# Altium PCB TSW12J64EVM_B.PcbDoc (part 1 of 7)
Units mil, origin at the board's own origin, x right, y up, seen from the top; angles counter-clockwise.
Board outline 8833 x 2680 mil, 10 copper layers (Top Layer L1, Gnd-Plane - L2, Signals - L3, Gnd-Plane - L4, Pwr Plane - L5, Signals - L6, Gnd-Plane - L7, Signals - L8, Gnd-Plane - L9, Bottom Layer - L10), stack 57.8 mil thick; 950 components, 533 nets, 2888 pads, 1732 vias.
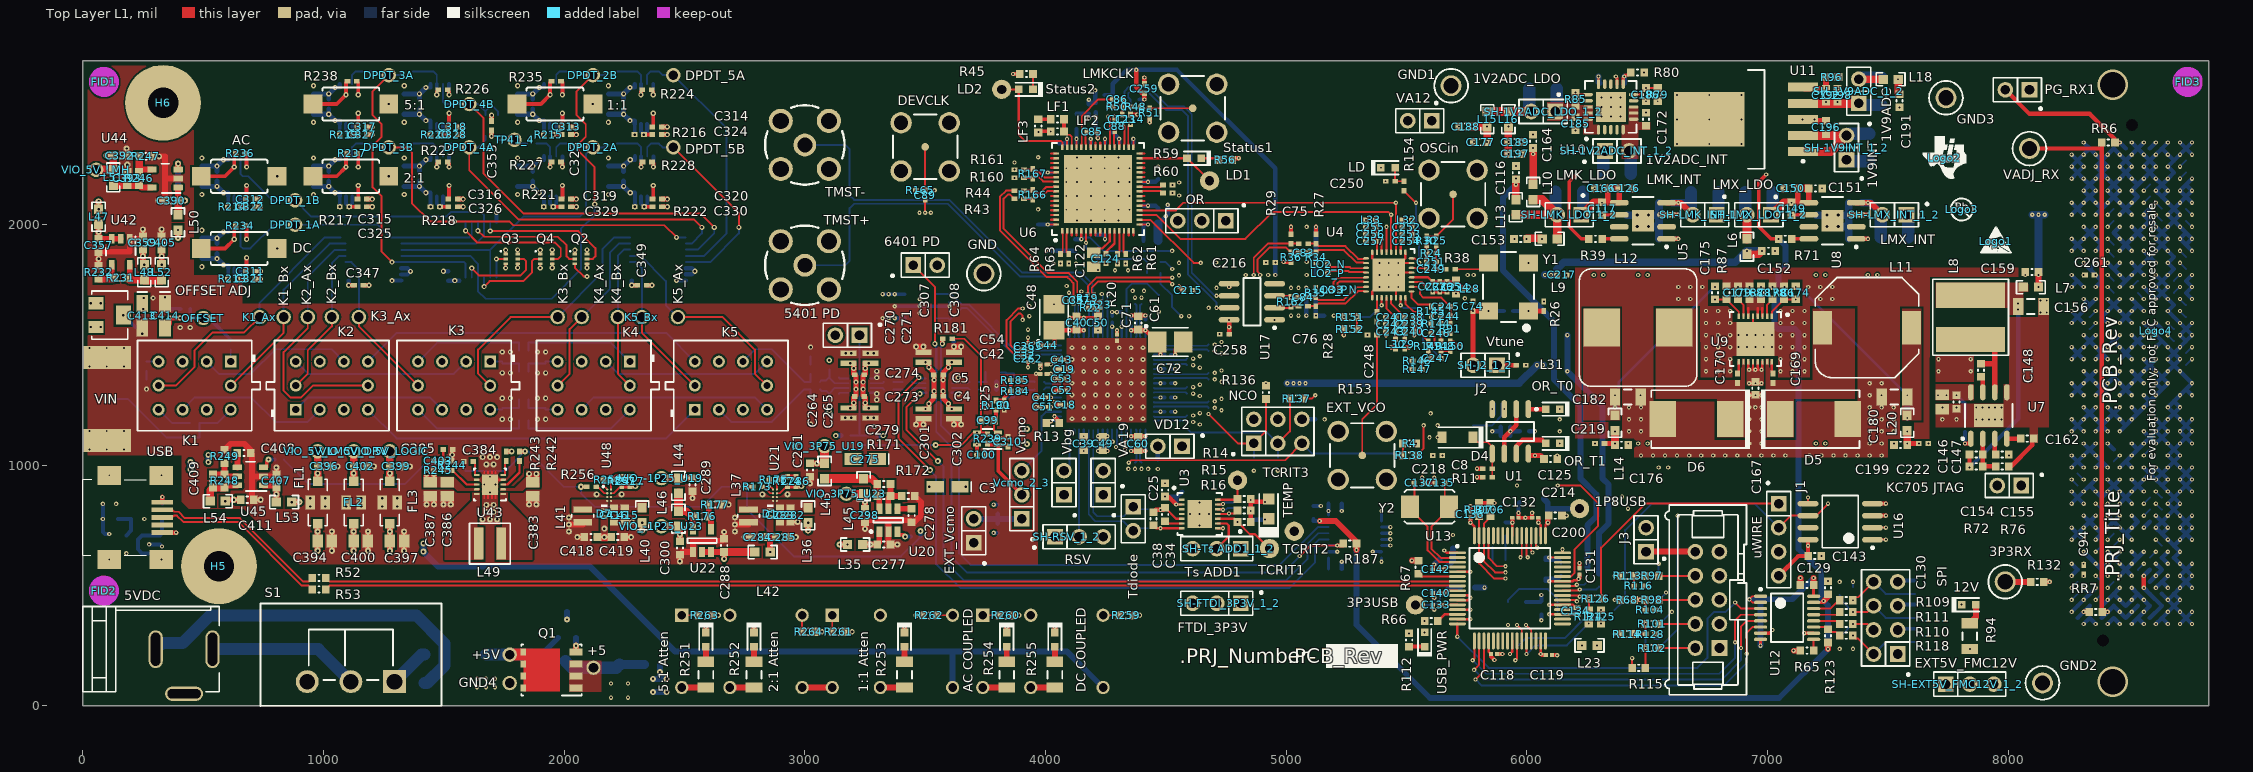
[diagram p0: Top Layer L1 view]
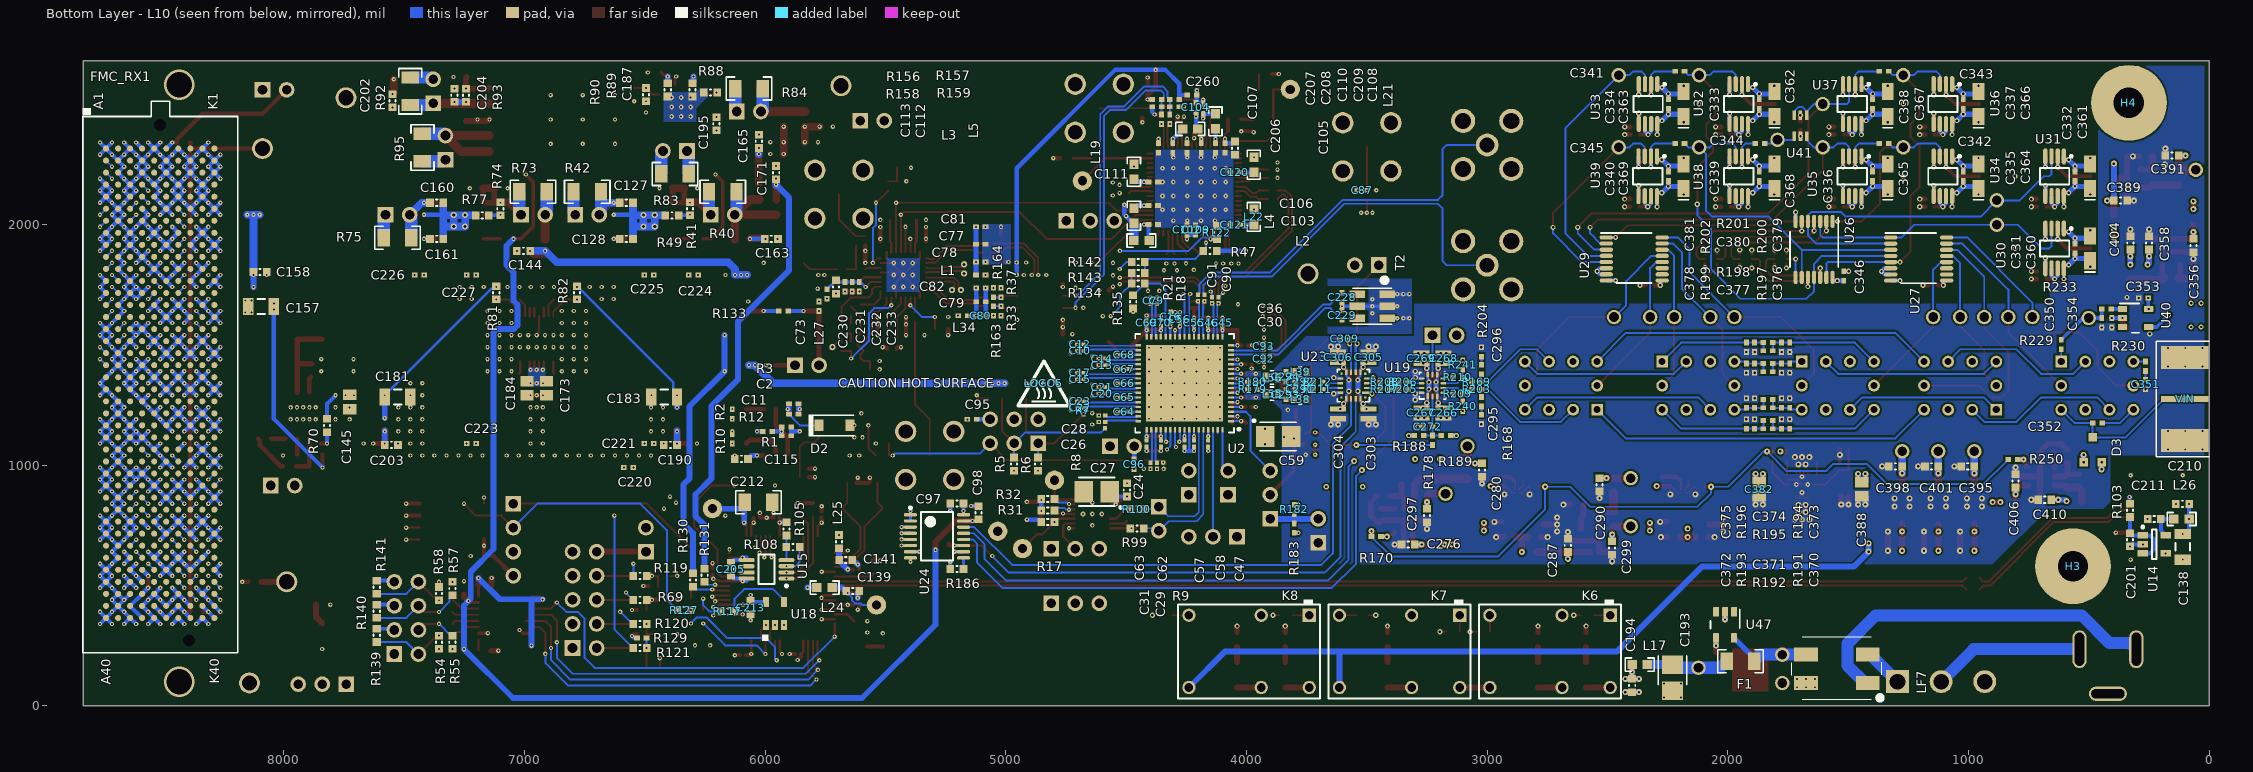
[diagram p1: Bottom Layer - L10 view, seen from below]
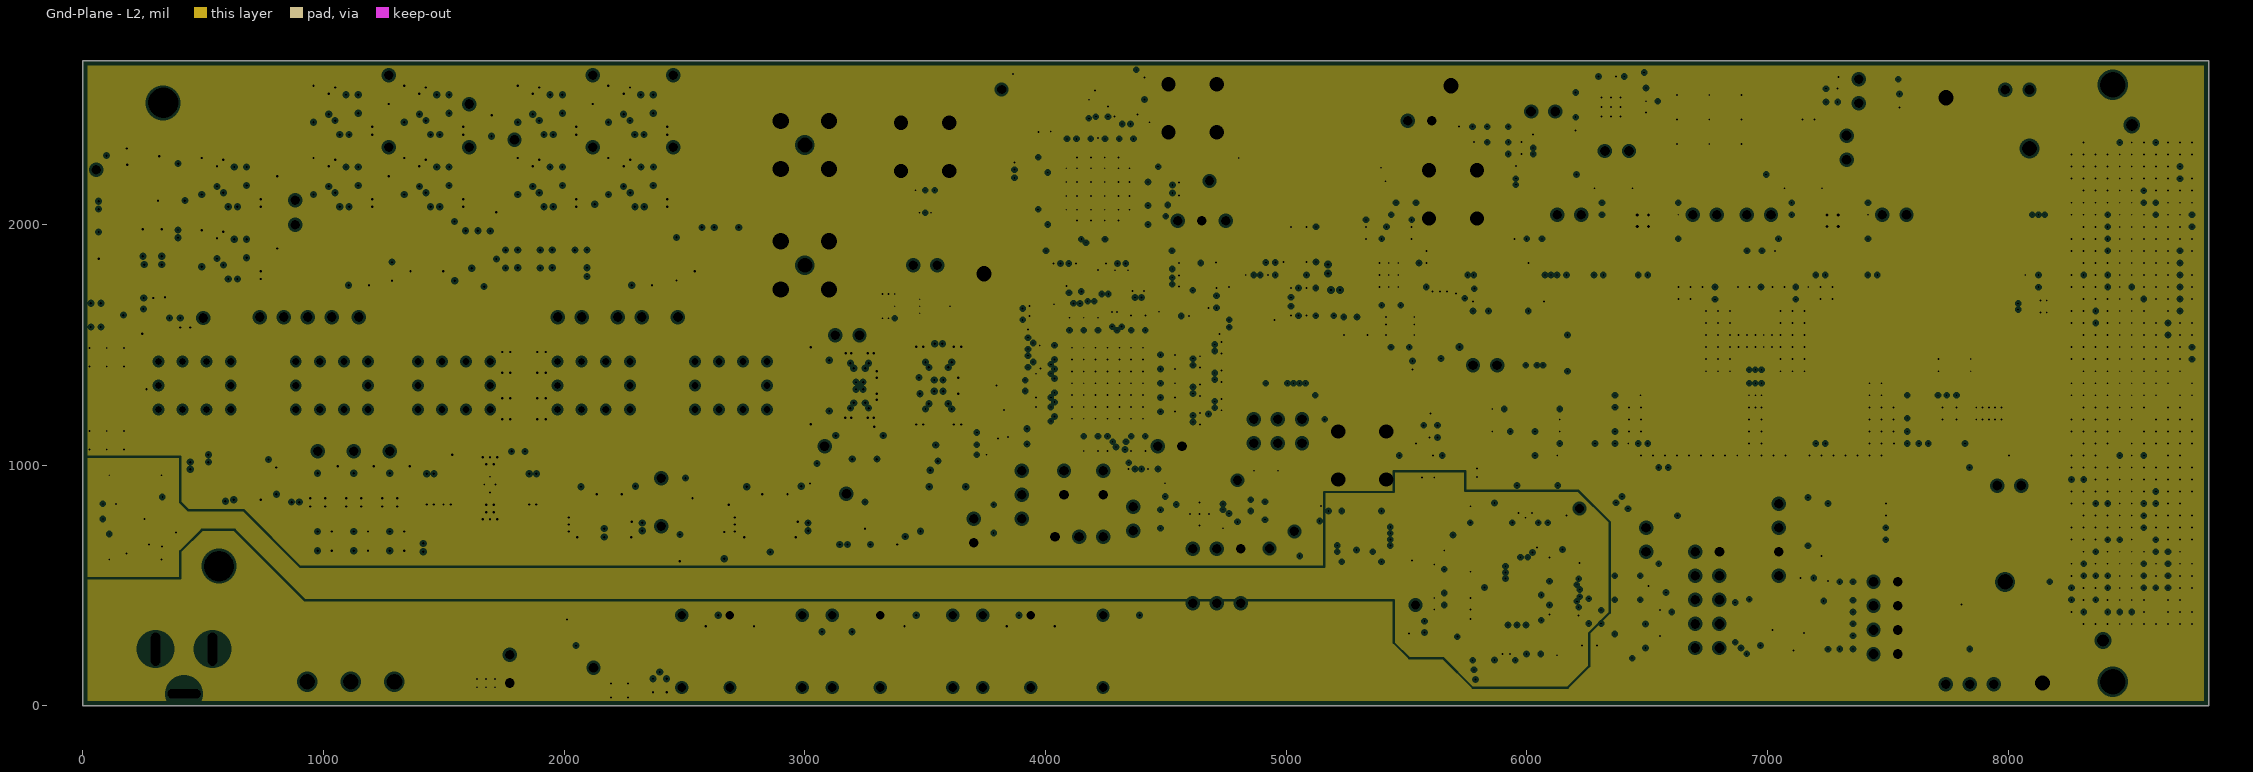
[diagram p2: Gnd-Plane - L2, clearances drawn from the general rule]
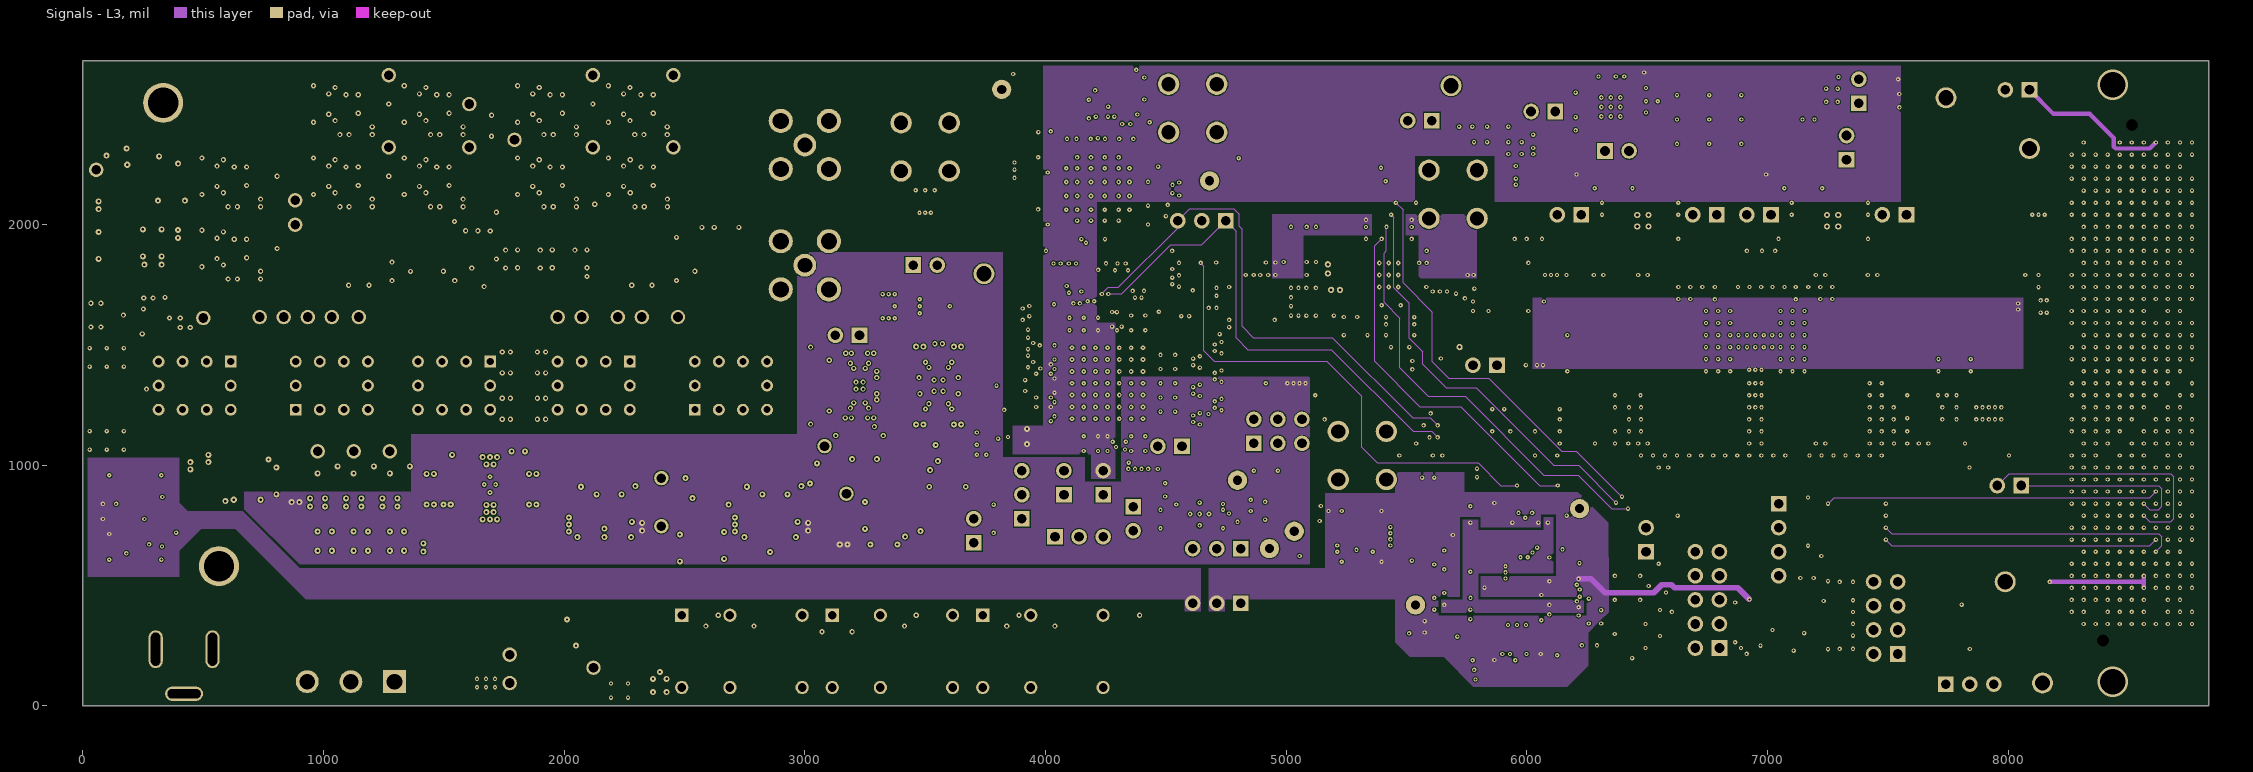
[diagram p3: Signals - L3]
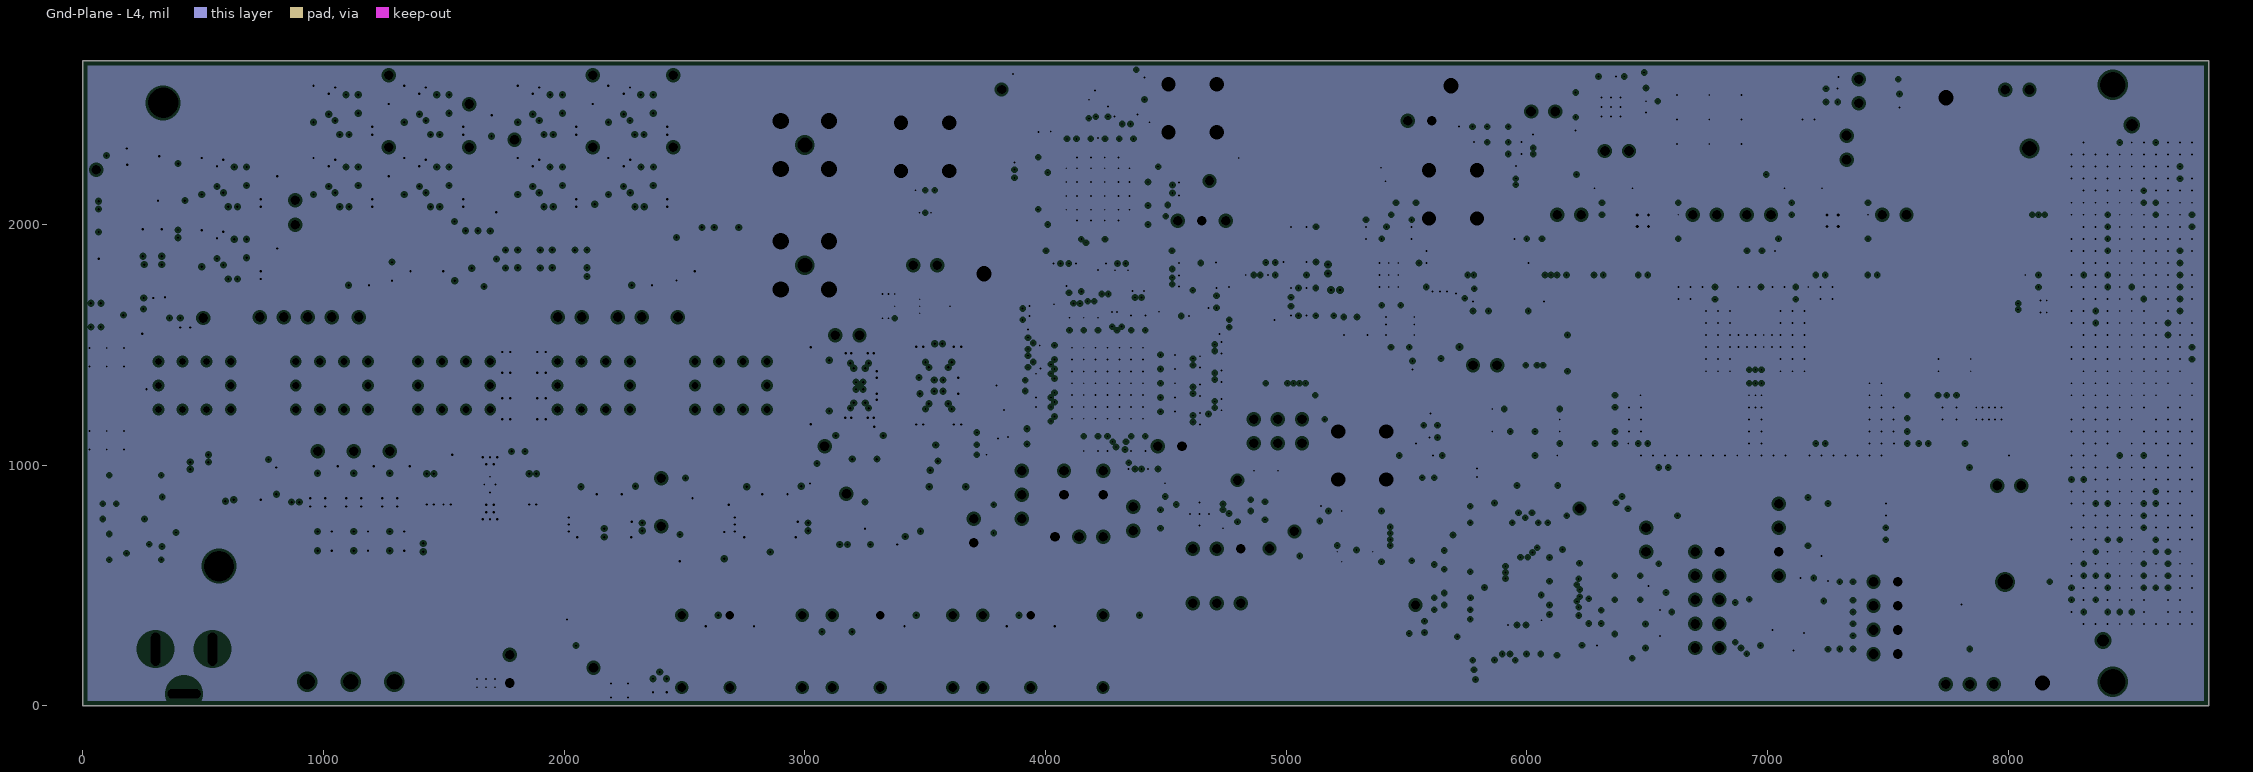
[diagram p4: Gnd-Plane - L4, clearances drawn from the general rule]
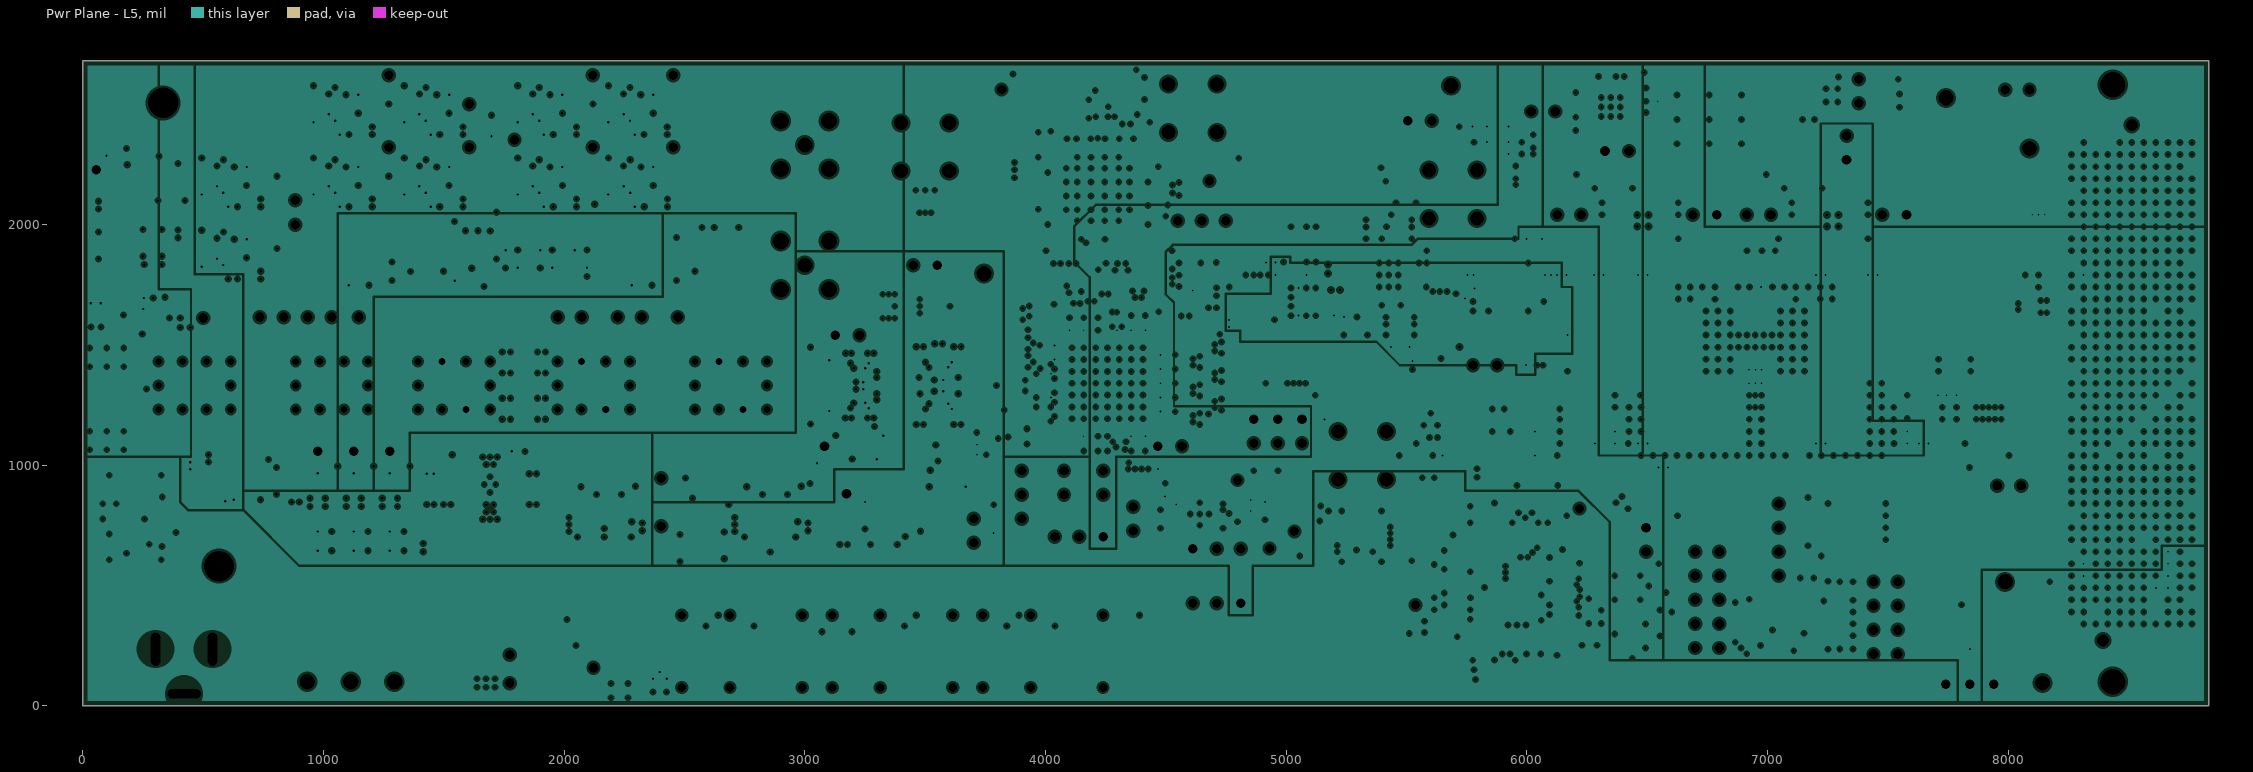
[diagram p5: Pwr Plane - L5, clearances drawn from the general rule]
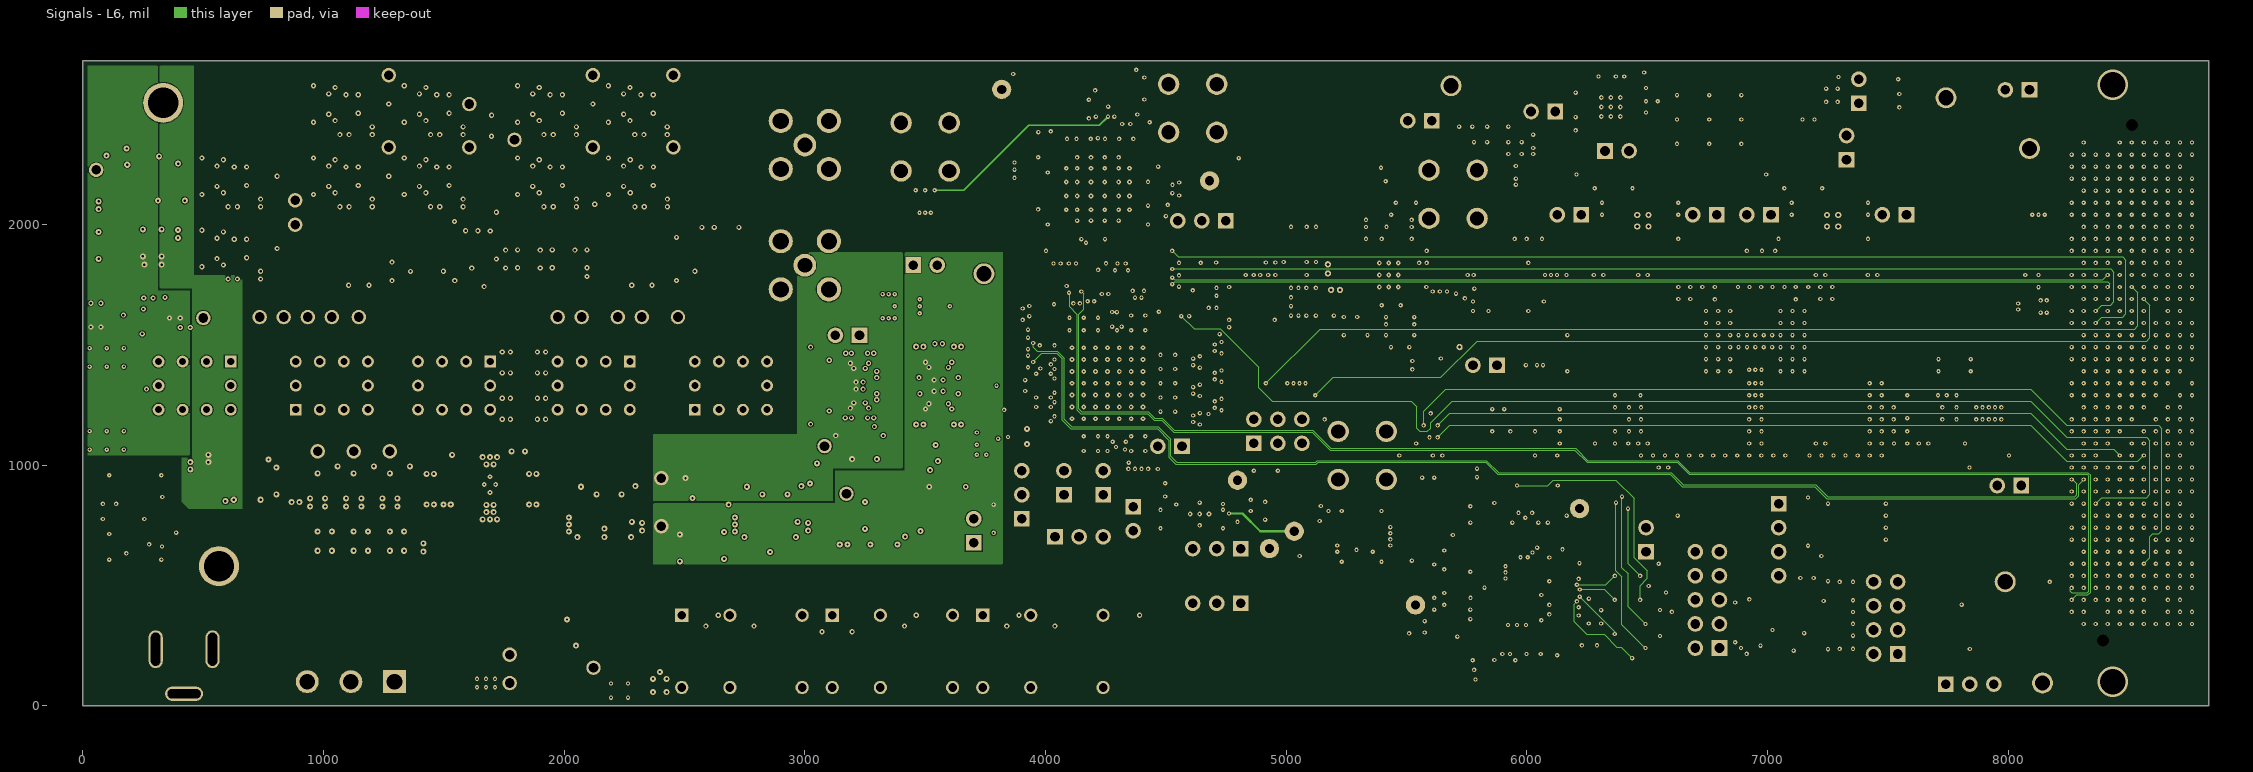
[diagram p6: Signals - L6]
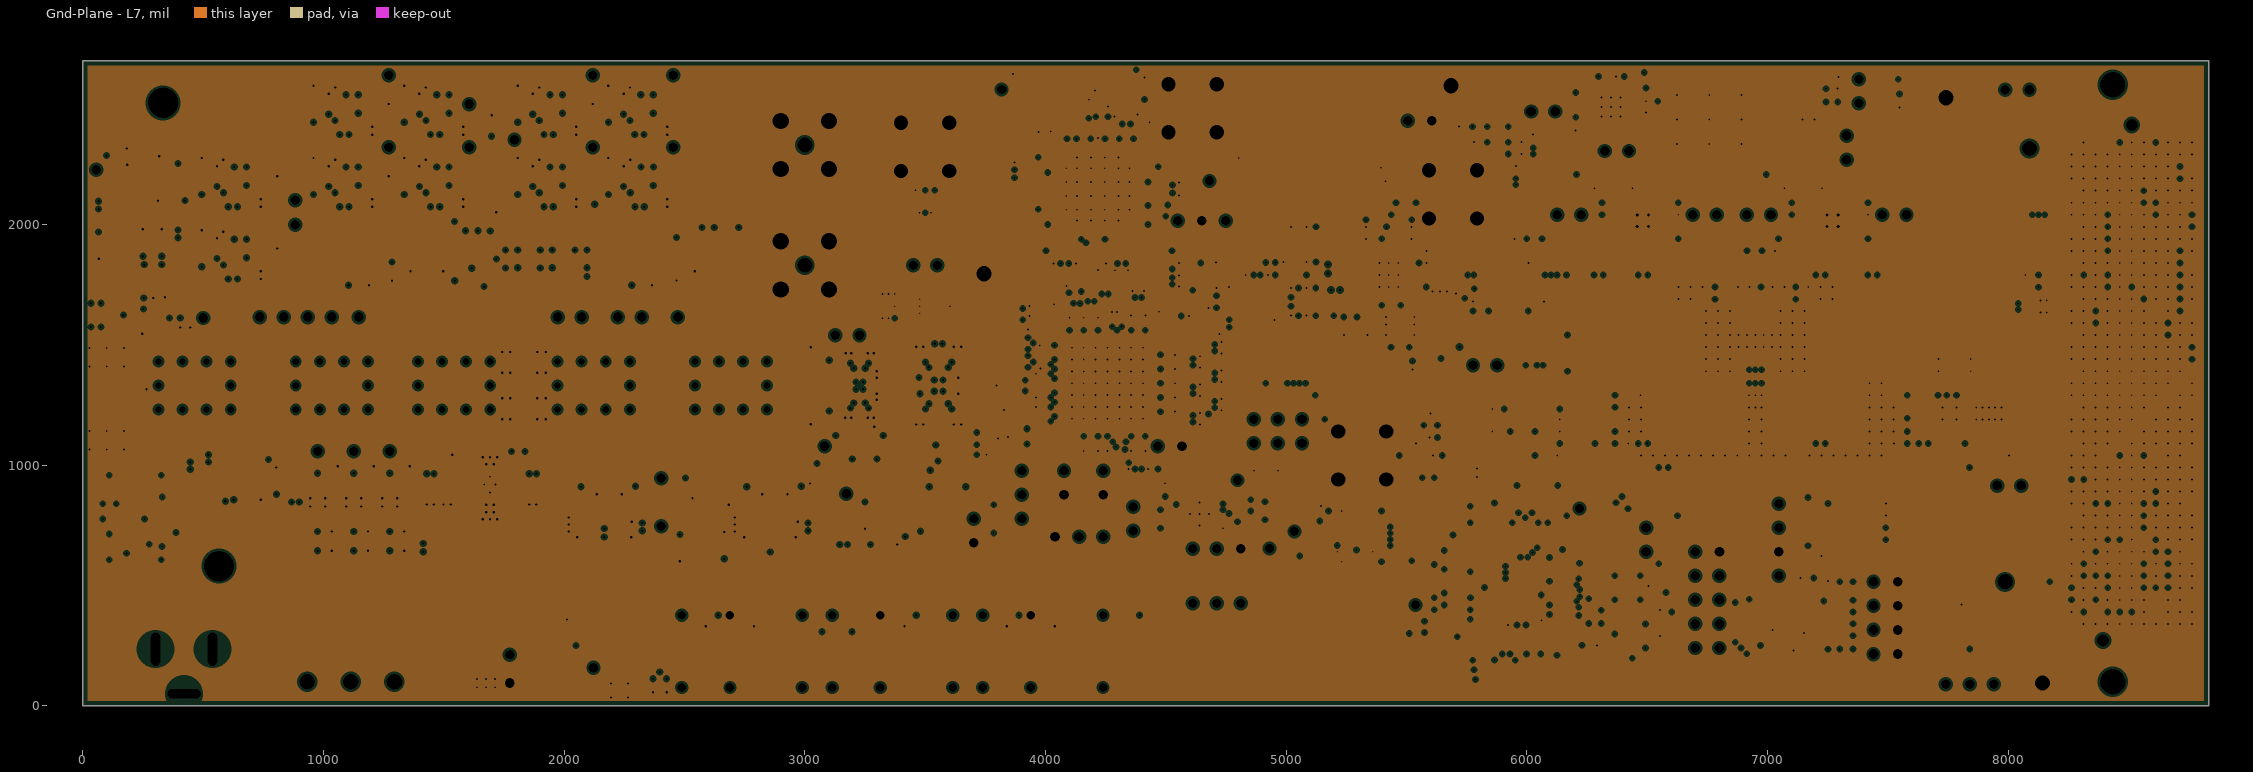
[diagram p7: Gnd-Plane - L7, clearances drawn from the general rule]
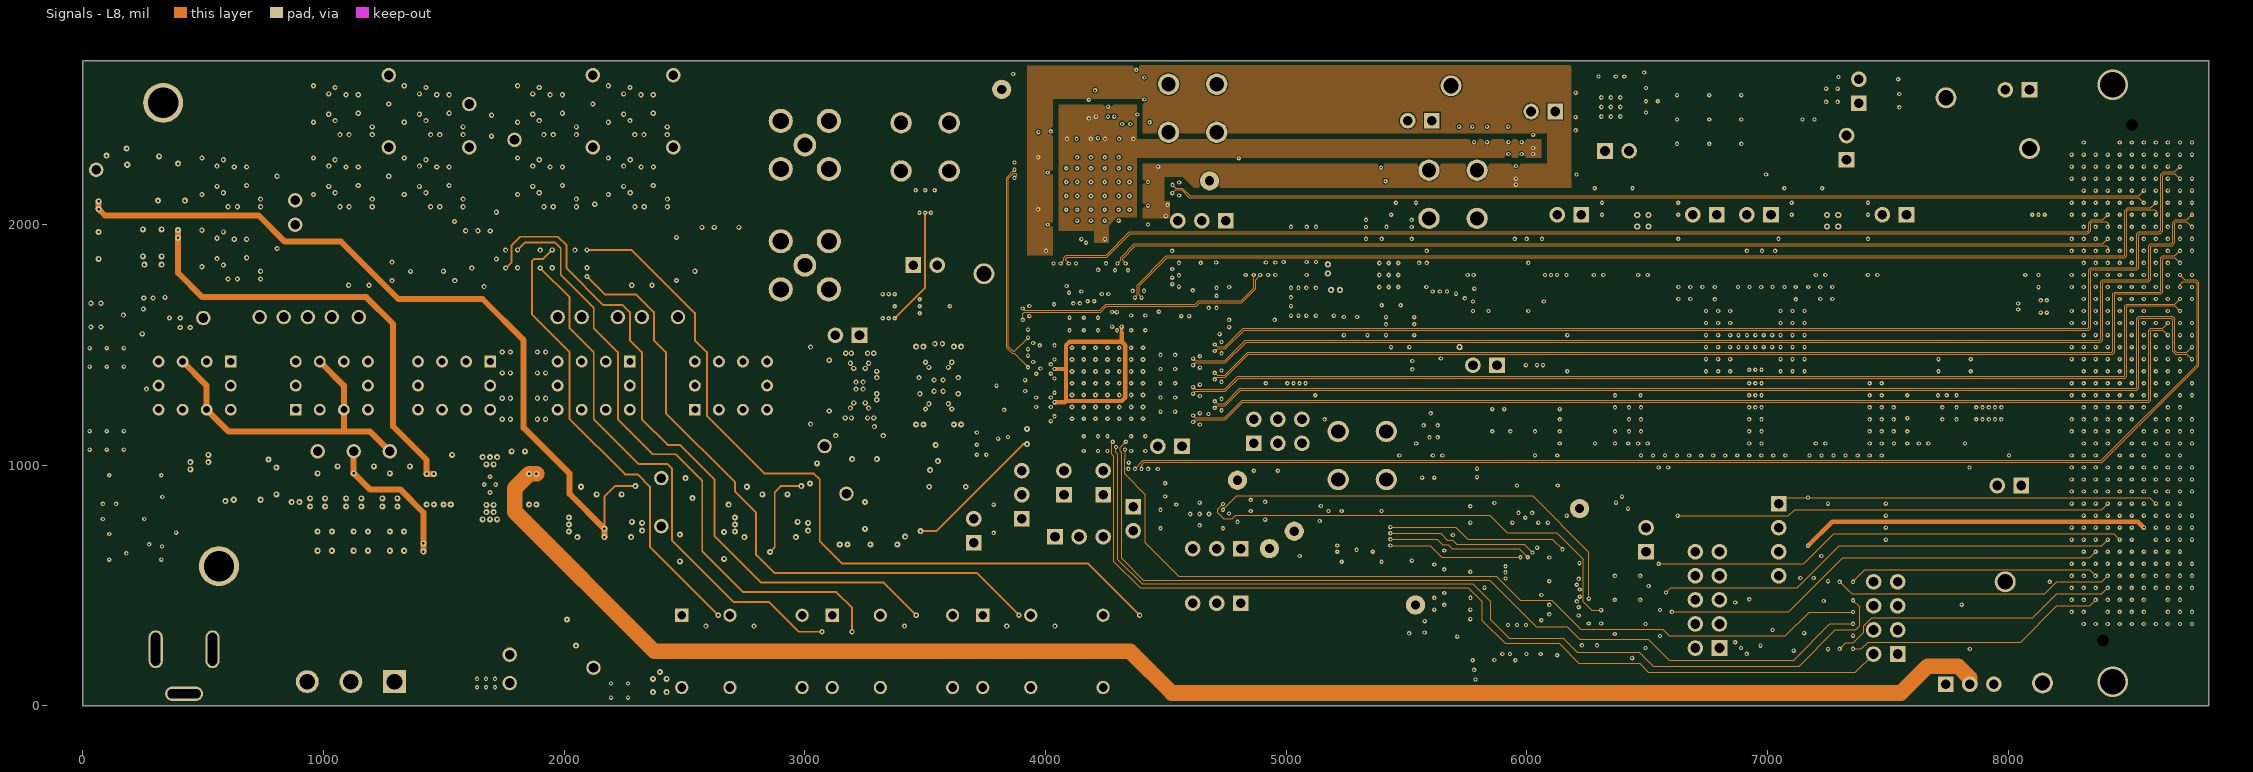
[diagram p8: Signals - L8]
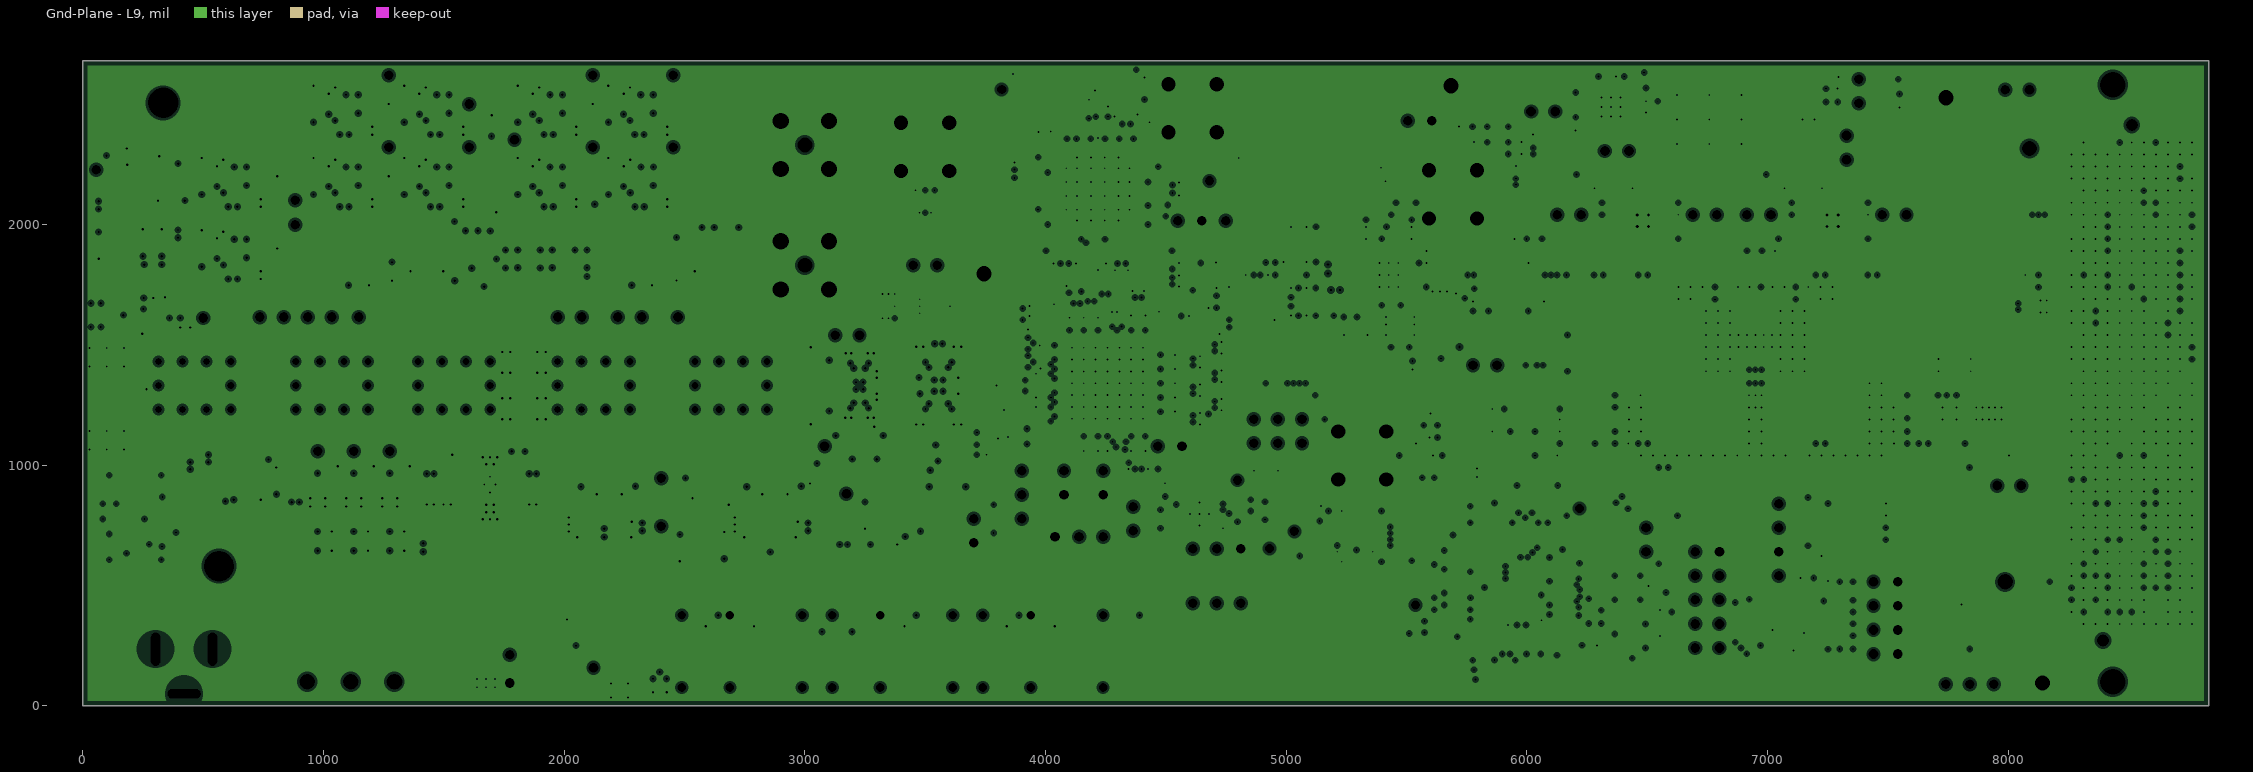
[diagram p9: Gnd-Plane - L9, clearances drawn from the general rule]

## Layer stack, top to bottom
Top Solder: solder mask 0.4, Solder Resist, Dk 3.5
Top Layer L1: signal copper 0.6
Dielectric1: core 4, Rogers RO4350, Dk 3.66
Gnd-Plane - L2: plane copper 1.2, net (Multiple Nets)
Dielectric8: prepreg 6.7, NP 4000-6, Dk 4.11
Signals - L3: signal copper 0.6
Dielectric2: core 6, NP 4000-6, Dk 4.11
Gnd-Plane - L4: plane copper 1.2, net GND
Dielectric7: prepreg 4.1, NP 4000-6, Dk 4.11
Pwr Plane - L5: plane copper 1.2, net (Multiple Nets)
Dielectric9: core 6, NP 4000-6, Dk 4.11
Signals - L6: signal copper 0.6
Dielectric3: prepreg 6.7, NP 4000-6, Dk 4.11
Gnd-Plane - L7: plane copper 1.2, net GND
Dielectric6: core 4, Rogers RO4350, Dk 3.66
Signals - L8: signal copper 0.6
Dielectric4: prepreg 7.3, Rogers RO4350, Dk 3.66
Gnd-Plane - L9: plane copper 1.2, net GND
Dielectric5: core 4, Rogers RO4350, Dk 3.66
Bottom Layer - L10: signal copper 0.6
Bottom Solder: solder mask 0.4, Solder Resist, Dk 3.5

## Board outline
0,0 8833,0 8833,2680 0,2680

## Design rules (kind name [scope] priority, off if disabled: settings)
AcuteAngle [All] p1: minimum=4.50000000000000E+0001 checktracksonly=FALSE
AssemblyTestPointUsage [All] p1: valid=2
Clearance Clearance_3 [InNamedPolygon('Top Layer L1-VIO_1P9V')] p1: gap=10
Clearance Clearance_2 [InNamedPolygon('Top Layer - L1 - Anolog In GND')] p2: gap=8
Clearance Clearance_1 [InNamedPolygon('Bottom Layer - L10 - Anolog In GND')] p3: gap=8
Clearance "0201 PADS" [HasFootprint('0201') vs HasFootprint('0201')] p4: gap=7.87
Clearance Clearance_BoardEdge_MountingHoles [OnCopper and InComponentClass('Mounting Holes') vs IsKeepOut] p5: gap=40
Clearance Clearance_BoardEdge_Poly [OnCopper and InPoly vs IsKeepOut] p6: gap=25
Clearance Clearance_BoardEdge [OnCopper and Not InComponentClass('Logo') and not InComponentClass('FiducialMark') and not InRegion(1000,500,4000,800) and Not IsKeepout vs IsKeepOut] p7: gap=25
Clearance [All] p8: gap=4
ComponentClearance ComponentClearance_R239_U25 [InComponent('R239') or InComponent('U25') vs InComponent('R239') or InComponent('U25')] p1: gap=0 collisioncheckmode=3 verticalgap=0 showdistances=FALSE
ComponentClearance ComponentClearance_FID2_5VDC [(InComponent('FID2') OR InComponent('5VDC'))] p2: gap=3.28 collisioncheckmode=3 verticalgap=3.28 showdistances=FALSE
ComponentClearance ComponentClearance_4-40_Screw [(HasFootprint('NY PMS 440 0025 PH'))] p3: gap=5 collisioncheckmode=3 verticalgap=10 showdistances=FALSE
ComponentClearance ComponentClearance_TestPoint [HasFootprint('TESTPOINT')] p4: gap=3.5 collisioncheckmode=3 verticalgap=10 showdistances=FALSE
ComponentClearance ComponentClearance_Shared_Pad [(InComponent('R7') OR InComponent('R8') OR InComponent('R9') OR InComponent('C22') OR InComponent('C26') OR InComponent('C29') OR InComponent('SH-*') OR InComponent('RSV*') OR InComponent('Ts ADD1*') OR InComponent('LMX_INT*') OR InComponent('LMX_LDO*') OR InComponent('LMK_INT*') OR InComponent('LMK_LDO*') OR InComponent('1V2ADC_INT*') OR InComponent('1V2ADC_LDO*') OR InComponent('1V9INT*') OR InComponent('1V9ADC*') OR InComponent('+12V*') OR InComponent('C32*') OR InComponent('C262*')OR InComponent('C33*') OR InComponent('C263*') OR InComponent('C92*') OR InComponent('C93*') OR InComponent('C89*') OR InComponent('R165*') OR InComponent('Vcmo_2_3*') OR InComponent('Vcmo*'))] p5: gap=0 collisioncheckmode=3 verticalgap=0 showdistances=FALSE
ComponentClearance ComponentClearance_0201 [HasFootprint('0201*') or HasFootprint('LQA68A') vs HasFootprint('0201*') or HasFootprint('LQA68A')] p6: gap=10 collisioncheckmode=3 verticalgap=10 showdistances=FALSE
ComponentClearance ComponentClearance_ScrewToNut [(HasFootprint('NY PMS 440 0025 PH')) vs (HasFootprint('Keystone_1902C'))] p7: gap=5 collisioncheckmode=3 verticalgap=10 showdistances=FALSE
ComponentClearance ComponentClearance_MountingHoles [InComponentClass('Mounting Holes')] p8: gap=250 collisioncheckmode=3 verticalgap=100000 showdistances=FALSE
ComponentClearance ComponentClearance_SmallPassives [HasFootprint('0201*') or HasFootprint('0402*') or HasFootprint('0508') or HasFootprint('0603*') or HasFootprint('0612') or HasFootprint('0805*') or HasFootprint('0815*') or HasFootprint('0830*') or HasFootprint('1206*') or HasFootprint('1210*') or HasFootprint('1808*') or HasFootprint('1812*') or HasFootprint('1825*') or HasFootprint('2010*') or HasFootprint('2220*') or HasFootprint('2225*') or HasFootprint('2512*') or HasFootprint('2728*') or HasFootprint('3518*') or HasFootprint('LQA68A*')  or HasFootprint('RTV0032A*') or HasFootprint('DBV0005A*') or HasFootprint('XTAL_ABM3*') or HasFootprint('RGW0020A*') or HasFootprint('M08A*') or HasFootprint('LED_LTST-C190*') or HasFootprint('DDA0008B*') or HasFootprint('SOIJ-SM8*') or HasFootprint('MSOP-MS8*') or HasFootprint('SDA16A*') or HasFootprint('OSC_CWX*') or HasFootprint('3528-21*') or HasFootprint('PW0016A*') or HasFootprint('MRA08A*') or HasFootprint('TJ5A*') or HasFootprint('SOD-123*') or HasFootprint('RLY0068A*') or HasFootprint('SOP-5_.95MM_(DBV)*') or HasFootprint('IND_2.0X2.0MM_A*') or HasFootprint('SOD-882*') or HasFootprint('YFX0008ADAC*') vs HasFootprint('0201*') or HasFootprint('0402*') or HasFootprint('0508') or HasFootprint('0603*') or HasFootprint('0612') or HasFootprint('0805*') or HasFootprint('0815*') or HasFootprint('0830*') or HasFootprint('1206*') or HasFootprint('1210*') or HasFootprint('1808*') or HasFootprint('1812*') or HasFootprint('1825*') or HasFootprint('2010*') or HasFootprint('2220*') or HasFootprint('2225*') or HasFootprint('2512*') or HasFootprint('2728*') or HasFootprint('3518*') or HasFootprint('LQA68A*')  or HasFootprint('RTV0032A*') or HasFootprint('DBV0005A*') or HasFootprint('XTAL_ABM3*') or HasFootprint('RGW0020A*') or HasFootprint('M08A*') or HasFootprint('LED_LTST-C190*') or HasFootprint('DDA0008B*') or HasFootprint('SOIJ-SM8*') or HasFootprint('MSOP-MS8*') or HasFootprint('SDA16A*') or HasFootprint('OSC_CWX*') or HasFootprint('3528-21*') or HasFootprint('PW0016A*') or HasFootprint('MRA08A*') or HasFootprint('TJ5A*') or HasFootprint('SOD-123*') or HasFootprint('RLY0068A*') or HasFootprint('SOP-5_.95MM_(DBV)*') or HasFootprint('IND_2.0X2.0MM_A*') or HasFootprint('SOD-882*') or HasFootprint('YFX0008ADAC*')] p9: gap=5 collisioncheckmode=3 verticalgap=5 showdistances=FALSE
ComponentClearance ComponentClearance_THtoSMT [IsThruComponent vs IsSMTComponent] p10: gap=10 collisioncheckmode=3 verticalgap=0 showdistances=FALSE
ComponentClearance ComponentClearance_THtoTH [IsThruComponent vs IsThruComponent] p11: gap=10 collisioncheckmode=3 verticalgap=100000 showdistances=FALSE
ComponentClearance [All] p12: gap=10 collisioncheckmode=3 verticalgap=10 showdistances=FALSE
DiffPairsRouting [All] p1: maxlimit=100 minlimit=4 mostfreqgap=4 toplayer_mingap=8 toplayer_prefgap=8 toplayer_minwidth=15 toplayer_maxwidth=15 toplayer_prefwidth=15 midlayer1_minwidth=15 midlayer1_maxwidth=15 midlayer1_prefwidth=15 midlayer2_minwidth=15 midlayer2_maxwidth=15 midlayer2_prefwidth=15 midlayer3_minwidth=15 midlayer3_maxwidth=15 midlayer3_prefwidth=15 bottomlayer_mingap=8 bottomlayer_prefgap=8 bottomlayer_minwidth=15 bottomlayer_maxwidth=15 bottomlayer_prefwidth=15 maxuncoupledlength=1000
FabricationTestPointUsage TestPointUsage [All] p1: valid=2 allowmultiple=FALSE
FabricationTestpoint Testpoint [All] p1: side=3 testpointundercomponent=TRUE minsize=40 maxsize=100 preferedsize=60 minholesize=0 maxholesize=40 preferedholesize=32 testpointgrid=1 allowsidetop=TRUE allowsidebottom=TRUE usegrid=TRUE gridtolerance=0.01
FanoutControl Fanout_LCC [IsLCC] p1: bgadir=Out bgaviamode=Centered fanoutstyle=Auto fanoutdirection=Alternating viagrid=1 // Fanout_LCC (Default Rule)
FanoutControl Fanout_BGA [IsBGA] p2: bgadir=Out bgaviamode=Centered fanoutstyle=Auto fanoutdirection=Alternating viagrid=1 // Fanout_BGA (Default Rule)
FanoutControl Fanout_Default [All] p4: bgadir=Out bgaviamode=Centered fanoutstyle=Auto fanoutdirection=Alternating viagrid=1 // Fanout_Default (Default Rule)
FanoutControl Fanout_Small [(CompPinCount < 5)] p5: bgadir=Out bgaviamode=Centered fanoutstyle=Auto fanoutdirection=OutThenIn viagrid=1 // Fanout_Small (Default Rule)
HoleSize [All] p1: absolutevalues=TRUE maxlimit=251 minlimit=7.87 maxpercent=80.000 minpercent=20.000
MinimumAnnularRing [All] p1: minimumring=5
MinimumSolderMaskSliver MinimumSolderMaskSliver_U21_U48 [All vs (InComponent('U21') OR InComponent('U48'))] p1: minsoldermaskwidth=3.74
MinimumSolderMaskSliver MinimumSolderMaskSliver_U19 [InComponent('U19')] p2: minsoldermaskwidth=3.5
MinimumSolderMaskSliver MinimumSolderMaskSliver_Logo [InComponentClass('Logo') vs InComponentClass('Logo')] p3: minsoldermaskwidth=0.7
MinimumSolderMaskSliver [All] p4: minsoldermaskwidth=4
NetAntennae "NetAntennae U2 or U6" [(InNet('U2-*') OR InNet('U6-*'))] p1: netantennaetolerance=50
NetAntennae [All] p2: netantennaetolerance=0
PlaneClearance [All] p1: clearance=10
PlaneConnect [All] p1: planeconnectstyle=Direct reliefexpansion=10 reliefentries=4 reliefconductorwidth=10 reliefairgap=10
PolygonConnect [All] p1: connectstyle=Direct reliefconductorwidth=10 reliefentries=4 polygonreliefangle="90 Angle" airgapwidth=10
RoutingVias [All] p1: holewidth=16 width=34 viastyle="Through Hole" minholewidth=7.87 minwidth=18 maxholewidth=106 maxwidth=126
SMDToCorner [All] p1: distance=30000
SilkToSilkClearance SilkToSilkClearance_Pb-FreeLogo [(HasFootprint('Pb-Free_Overlay_Medium') OR HasFootprint('Pb-Free_Overlay_Small')) vs (HasFootprint('Pb-Free_Overlay_Medium') OR HasFootprint('Pb-Free_Overlay_Small'))] p1: silktosilkclearance=0
SilkToSilkClearance [All] p2: silktosilkclearance=5
SilkToSolderMaskClearance SilkscreenOverComponentPads [IsPad] p1: minsilkscreentomaskgap=5 clearancetoexposedcopper=TRUE
SolderMaskExpansion [All] p1: expansion=3
UnpouredPolygon [All] p1: allowunpoured=FALSE
Width [All] p1: maxlimit=100 minlimit=4 preferedwidth=10 checkconnectedcopper=TRUE
13 further rules are at their usual default settings.

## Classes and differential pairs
component class AssemblyNote: !PCB H9 H10 H11 H12 ZZ2 ZZ3 ZZ4
component class Header: 1V2ADC_INT 1V2ADC_LDO 1V9ADC 1V9INT "5401 PD" "6401 PD" EXT5V_FMC12V EXT_Vcmo FTDI_3P3V J1 J2 J3 "KC705 JTAG" LMK_INT LMK_LDO LMX_INT LMX_LDO NCO OR PG_RX1 RSV SPI Tdiode "Ts ADD1" VA12 VA19 Vbg Vcmo VD12
component class Shunt: SH-1V2ADC_INT_1_2 SH-1V2ADC_LDO_1_2 SH-1V9ADC_1_2 SH-1V9INT_1_2 SH-EXT5V_FMC12V_1_2 SH-FTDI_3P3V_1_2 SH-J2_1_2 SH-LMK_INT_1_2 SH-LMK_LDO_1_2 SH-LMX_INT_1_2 SH-LMX_LDO_1_2 SH-RSV_1_2 "SH-Ts ADD1_1_2" Vcmo_2_3
component class 0402L: C1 C272 C309
component class FiducialMark: FID1 FID2 FID3
component class Logo: Logo2
component class "Mounting Holes": H5 H6
differential pair IN: +IN_P -IN_N
differential pair DEV_CLK: +DEV_CLK_P -DEV_CLK_N
differential pair CLK10: +CLK10_P -CLK10_N
differential pair TMST: +TMST_P -TMST_N
differential pair CLK3: +CLK3_P -CLK3_N
differential pair CLK11: +CLK11_P -CLK11_N
differential pair CLK0: +CLK0_P -CLK0_N
differential pair CLK4: +CLK4_P -CLK4_N
differential pair CLKIN1: +CLKIN1_P -CLKIN1_N
differential pair D0: +D0_P -D0_N
differential pair D1: +D1_P -D1_N
differential pair D2: +D2_P -D2_N
differential pair D3: +D3_P -D3_N
differential pair D4: +D4_P -D4_N
differential pair D5: +D5_P -D5_N
differential pair D6: +D6_P -D6_N
differential pair D7: +D7_P -D7_N
differential pair DEVCLKARX: +DEVCLKARX_P -DEVCLKARX_N
differential pair DEVCLKBRX: +DEVCLKBRX_P -DEVCLKBRX_N
differential pair DEVCLK: +DEVCLK_P -DEVCLK_N
differential pair SYNC: +SYNC_P -SYNC_N
differential pair SYSREFRX: +SYSREFRX_P -SYSREFRX_N
differential pair SYSREFTX: +SYSREFTX_P -SYSREFTX_N
differential pair SYSRF: +SYSRF_P -SYSRF_N
differential pair VIN: +VIN_P -VIN_N
differential pair SYNC~/TMST: +SYNC~/TMST_P -SYNC~/TMST_N
differential pair LO1: +LO1_P -LO1_N
differential pair LO2: +LO2_P -LO2_N
differential pair LO3: +LO3_P -LO3_N
differential pair LO4: +LO4_P -LO4_N
differential pair TRF_OUTA: +TRF_OUTA_P -TRF_OUTA_N
differential pair TRF_OUTB: +TRF_OUTB_P -TRF_OUTB_N
differential pair FMC_SYSREF: +FMC_SYSREF_P -FMC_SYSREF_N
differential pair FMC_DEVCLK: +FMC_DEVCLK_P -FMC_DEVCLK_N

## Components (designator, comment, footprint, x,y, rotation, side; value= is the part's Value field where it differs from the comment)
1:1 "RS-032G05A3-SM RT" SW_RS-032G05A3-SM 1962,2500 r180 top
"1:1 Atten" "LTST-C190GKT" LED_LTST-C190 3414,275 r90 top
1P8USB "TESTPOINT" TESTPOINT#1 6219,819 r90 top
1V2ADC_INT "TSW-102-07-G-S" TSW-102-07-G-S 6374.27,2305 r0 top
1V2ADC_LDO "TSW-102-07-G-S" TSW-102-07-G-S 6067.27,2469 r180 top
1V9ADC "TSW-102-07-G-S" TSW-102-07-G-S 7379,2552.93 r90 top
1V9INT "TSW-102-07-G-S" TSW-102-07-G-S 7328,2319.07 r90 top
2:1 "RS-032G05A3-SM RT" SW_RS-032G05A3-SM 1114,2200 r180 top
"2:1 Atten" "LTST-C190GKT" LED_LTST-C190 2789,275 r90 top
3P3RX "5011" Keystone5011 7987,515 r90 top
3P3USB "TESTPOINT" TESTPOINT#1 5537,419 r90 top
5:1 "RS-032G05A3-SM RT" SW_RS-032G05A3-SM 1114,2500 r180 top
"5:1 Atten" "LTST-C190GKT" LED_LTST-C190 2589,275 r90 top
5VDC "PJ-202AH" CONN_CUI-PJ-202AH 539.37,235 r180 top
12V "LTST-C190GKT" LED_LTST-C190 7835.47,420 r180 top
"5401 PD" "TSW-102-07-G-S" TSW-102-07-G-S 3177.22,1539 r180 top
"6401 PD" "TSW-102-07-G-S" TSW-102-07-G-S 3500.06,1831 r0 top
+5 "TESTPOINT" TP_VIA_060RND040 2122,158 r0 top
+5V "TESTPOINT" TP_VIA_060RND040 1774,212.6 r0 top
AC "RS-032G05A3-SM RT" SW_RS-032G05A3-SM 650,2200 r180 top
"AC COUPLED" "LTST-C190GKT" LED_LTST-C190 3839,275 r90 top
C1 "C1005X7R1E103K" 0402L#1 3828.43,1249 r90 top
C2 "GRM155R71A104KA01D" 0402L#1 5881,1210.67 r180 bottom
C3 "TPSA106K010R0900" 3216-18 3593,910 r180 top
C4 "C1005X5R1A104K" 0402L#1 3555.88,1286.06 r180 top
C5 "C1005X5R1A104K" 0402L#1 3555.88,1374.26 r180 top
C7 "C0603X5R0J104K" 0201#1 4398.84,1682.81 r270 bottom
C8 "GRM155R71A104KA01D" 0402L#1 5836.32,985 r180 top
C9 "C0603X5R0J104K" 0201#1 4371.84,1682.81 r270 bottom
C10 "C0603X5R0J104K" 0201#1 4690.19,1474.14 r180 bottom
C11 "GRM155R71A104KA01D" 0402L#1 5911.31,1158 r180 bottom
C12 "C0603X5R0J104K" 0201#1 4690.19,1501.14 r180 bottom
C13 "C0603X5R0J104K" 0201#1 4600.19,1415.08 r180 bottom
C14 "C0603X5R0J104K" 0201#1 4600.19,1442.08 r180 bottom
C15 "C0603X5R0J104K" 0201#1 4690.19,1356.03 r180 bottom
C16 "C1005X5R0J475M050BC" 0402L#1 4315,1615.62 r270 bottom
C17 "C0603X5R0J104K" 0201#1 4690.19,1383.03 r180 bottom
C18 "C1005X5R1A104K" 0402L#1 4082.26,1251.2 r180 top
C19 "C1005X5R1A104K" 0402L#1 4077.2,1399.05 r180 top
C20 "C0603X5R0J104K" 0201#1 4600.19,1296.97 r180 bottom
C21 "C0603X5R0J104K" 0201#1 4600.19,1323.97 r180 bottom
C22 "C0603X5R0J104K" 0201#1 4690.19,1237.92 r180 bottom
C23 "C0603X5R0J104K" 0201#1 4690.19,1264.92 r180 bottom
C24 "0603YC104JAT2A" 0603L#1 4497.28,897.03 r90 bottom
C25 "06035A101JAT2A" 0603L#1 4497.28,897.03 r90 top
C26 "C0603X5R0J104K" 0201#1 4600.19,1178.86 r180 bottom
C27 "293D106X0010B2TE3" 3528-21#1 4622.28,889.42 r0 bottom
C28 "C0603X5R0J104K" 0201#1 4600.19,1205.86 r180 bottom
C29 "C0603X5R0J104K" 0201#1 4371.84,997.19 r90 bottom
C30 "C0603X5R0J224M" 0201#1 3914.58,1454.45 r180 bottom
C31 "C0603X5R0J104K" 0201#1 4398.84,997.19 r90 bottom
C32 "GRM033R61A472KA01D" 0201#1 3914.58,1454.45 r180 top
C33 "GRM033R61A472KA01D" 0201#1 3914.58,1481.45 r180 top
C34 "06035A101JAT2A" 0603L#1 4497.28,795 r90 top
C35 "GRM033R61A472KA01D" 0201#1 4115.93,1685 r90 top
C36 "C0603X5R0J224M" 0201#1 3914.58,1481.45 r180 bottom
C37 "GRM033R61A472KA01D" 0201#1 4142.94,1685 r90 top
C38 "06035A101JAT2A" 0603L#1 4448.28,777 r90 top
C39 "C1608X5R1A105K" 0603L#1 4158.96,1089.26 r270 top
C40 "C1608X5R1A105K" 0603L#1 4129.43,1590.74 r90 top
C41 "C0603X5R0J104K" 0201#1 3991.65,1280.94 r0 top
C42 "C0603X5R0J104K" 0201#1 3991.65,1379.37 r0 top
C43 "C0603X5R0J104K" 0201#1 4067.87,1438.43 r180 top
C44 "C0603X5R0J104K" 0201#1 4006.65,1497.48 r0 top
C45 "C0603X5R0J104K" 0201#1 4099.91,1590.74 r270 bottom
C46 "C0603X5R0J104K" 0201#1 4158.96,1590.74 r270 bottom
C47 "C0603X5R0J104K" 0201#1 4158.96,1089.26 r90 bottom
C48 "293D106X0010B2TE3" 3528-21#1 4035,1614 r90 top
C49 "C1608X5R1A105K" 0603L#1 4237.7,1089.26 r270 top
C50 "C1608X5R1A105K" 0603L#1 4218.02,1590.74 r90 top
C51 "C0603X5R0J104K" 0201#1 3991.65,1241.57 r0 top
C52 "C0603X5R0J104K" 0201#1 4070.57,1310.95 r180 top
C53 "C0603X5R0J104K" 0201#1 4067.87,1359.68 r180 top
C54 "C0603X5R0J104K" 0201#1 3991.65,1418.74 r0 top
C55 "C0603X5R0J104K" 0201#1 4218.02,1590.74 r270 bottom
C56 "C0603X5R0J104K" 0201#1 4277.07,1605.74 r270 bottom
C57 "C0603X5R0J104K" 0201#1 4257.39,1089.26 r90 bottom
C58 "C0603X5R0J104K" 0201#1 4218.02,1089.26 r90 bottom
C59 "293D106X0010B2TE3" 3528-21#1 3868.87,1118.87 r180 bottom
C60 "C1608X5R1A105K" 0603L#1 4385.34,1089.26 r270 top
C61 "C1608X5R1A105K" 0603L#1 4385.34,1590.74 r90 top
C62 "C0603X5R0J104K" 0201#1 4355.81,1089.26 r90 bottom
C63 "C0603X5R0J104K" 0201#1 4414.87,1089.26 r90 bottom
C64 "C0603X5R0J104K" 0201#1 4508.13,1221.89 r180 bottom
C65 "C0603X5R0J104K" 0201#1 4508.13,1280.95 r180 bottom
C66 "C0603X5R0J104K" 0201#1 4508.13,1340 r180 bottom
C67 "C0603X5R0J104K" 0201#1 4508.13,1399.05 r180 bottom
C68 "C0603X5R0J104K" 0201#1 4508.13,1458.11 r180 bottom
C69 "C0603X5R0J104K" 0201#1 4414.87,1590.74 r270 bottom
C70 "C0603X5R0J104K" 0201#1 4355.81,1590.74 r270 bottom
C71 "C0603X5R0J104K" 0201#1 4296.76,1529.51 r90 top
C72 "293D106X0010B2TE3" 3528-21#1 4518.39,1511.4 r0 top
C73 "C1005X5R1A104K" 0402L#1 5776,1659.68 r270 bottom
C74 "GRM1555C1E101JA01D" 0402L#1 5776,1659.68 r270 top
C75 "GRM1555C1H470JA01D" 0402L#1 5072.05,1919.81 r180 top
C76 "GRM1555C1H470JA01D" 0402L#1 5071.05,1660.18 r180 top
C77 "GRM155R71E103KA01D" 0402L#1 5104.36,1917 r180 bottom
C78 "GRM1555C1H270JA01D" 0402L#1 5104.36,1843.81 r180 bottom
C79 "GRM155R71E103KA01D" 0402L#1 5103.36,1678.5 r180 bottom
C80 "GRM1555C1H270JA01D" 0402L#1 5103.36,1620.82 r180 bottom
C81 "C1005X5R0J105M" 0402L#1 5104.36,1990 r180 bottom
C82 "C1005X5R0J105M" 0402L#1 5103.36,1736.18 r180 bottom
C83 "GRM1555C1H470JA01D" 0402L#1 5072.05,1883.18 r180 top
C84 "GRM1555C1H470JA01D" 0402L#1 5071.05,1696.81 r180 top
C85 "C1005X5R1A104K" 0402L#1 4194,2384 r180 top
C86 "C1005X5R1A104K" 0402L#1 4298.98,2519 r180 top
C87 "C1005X5R1A104K" 0402L#1 3519.74,2141.68 r180 bottom
C88 "C1005X5R1A104K" 0402L#1 4288,2407 r90 top
C89 "C1005X5R1A104K" 0402L#1 3500.06,2122 r270 top
C90 "GRM033R61A472KA01D" 0201#1 4115.93,1685 r90 bottom
C91 "GRM033R61A472KA01D" 0201#1 4142.94,1685 r90 bottom
C92 "GRM033R61A472KA01D" 0201#1 3927.57,1441.46 r270 bottom
C93 "GRM033R61A472KA01D" 0201#1 3927.57,1494.45 r90 bottom
C94 "GRM155R71A104KA01D" 0402L#1 8313,565 r270 top
C95 "GRM155R71A104KA01D" 0402L#1 5140,1190 r180 bottom
C96 "GRM155R71A104KA01D" 0402L#1 4467,1003.5 r90 bottom
C97 "06033C104JAT2A" 0603L#1 5203.13,840 r0 bottom
C98 "06033C104JAT2A" 0603L#1 5113.28,802.28 r90 bottom
C99 "C1608X5R1A105K" 0603L#1 3759.12,1186 r0 top
C100 "C1005X5R1A104K" 0402L#1 3734.51,1043 r0 top
C102 "C1005X7R1C103K" 0402L#1 4247.09,1977.24 r90 bottom
C103 "C1005X5R1A104K" 0402L#1 4387.32,1999.36 r180 bottom
C104 "C1005X5R1A104K" 0402L#1 4210.05,2486.05 r90 bottom
C105 "C1005X5R1A104K" 0402L#1 4306.14,2316.76 r270 bottom
C106 "C1005X5R1A104K" 0402L#1 4387.32,2078.1 r180 bottom
C107 "C1005X5R1A104K" 0402L#1 4179.92,2479.18 r90 bottom
C108 "C1608X5R1C105K" 0603L#1 4047.92,2316.76 r270 bottom
C109 "C1005X5R1A104K" 0402L#1 4211.72,1977.24 r90 bottom
C110 "C1005X5R1A104K" 0402L#1 4128.98,2316.76 r270 bottom
C111 "C1005X5R1A104K" 0402L#1 4387.32,2176.53 r180 bottom
C112 "C1005X5R1A104K" 0402L#1 4318.67,2437 r90 bottom
C113 "C1005X5R1A104K" 0402L#1 4352.67,2437 r90 bottom
C114 "C1005X5R1A104K" 0402L#1 4352.67,2437 r270 top
C115 "0603YC104JAT2A" 0603L#1 6098.49,1026 r0 bottom
C116 "06033C104JAT2A" 0603L#1 5954,2215 r90 top
C117 "06035A331JAT2A" 0603L#1 6312,2065 r270 top
C118 "C0603X5R0J104K" 0201#1 5863.72,215.03 r0 top
C119 "C0603X5R0J104K" 0201#1 6091.47,210.03 r0 top
C120 "C1005X5R1A104K" 0402L#1 4047.8,2215.9 r0 bottom
C121 "C1005X5R1A104K" 0402L#1 4047.8,1999.36 r0 bottom
C122 "C0805C106K8PACTU" 0805L 4200.9,1852.74 r270 top
C123 "C1005X5R1A104K" 0402L#1 4318.67,2437 r90 top
C124 "C1005X5R1A104K" 0402L#1 4251.3,1857.74 r270 top
C125 "C1608X5R1A105K" 0603L#1 6098.49,1026 r0 top
C126 "06033C104JAT2A" 0603L#1 6411.13,2150 r0 top
C127 "C0603C475K8PACTU" 0603L#1 6576.49,2090 r180 bottom
C128 "06031C103MAT2A" 0603L#1 6576.49,1940 r180 bottom
C129 "06033C104JAT2A" 0603L#1 7163.68,502.06 r180 top
C130 "06033C104JAT2A" 0603L#1 7251,490.31 r90 top
C131 "C0603X5R0J104K" 0201#1 6218.44,558.42 r90 top
C132 "C0603X5R0J104K" 0201#1 5952.31,781.24 r0 top
C133 "C0603X5R0J104K" 0201#1 5622.45,419.1 r180 top
C134 "C0603X5R0J104K" 0201#1 6202.44,394.5 r270 top
C135 "GRM1555C1H180JA01D" 0402L#1 5638.97,926 r180 top
C136 "C0603X5R0J104K" 0201#1 5765,795.02 r90 top
C137 "GRM1555C1H180JA01D" 0402L#1 5551.98,926 r0 top
C138 "GRM31CR60J107ME39L" 1206L 110.24,660.39 r270 bottom
C139 "C1608X5R1A106M" 0603L#1 5635.75,477.1 r180 bottom
C140 "C0603X5R0J104K" 0201#1 5622.45,468.32 r180 top
C141 "C1608X5R1A106M" 0603L#1 5665,606 r180 bottom
C142 "C0603X5R0J104K" 0201#1 5622.45,566.74 r180 top
C143 "C1608X5R1A105K" 0603L#1 7195.7,622 r0 top
C144 "06033C104JAT2A" 0603L#1 7004,1890 r0 bottom
C145 "EMK212BJ106KG-T" 0805L 7726,1262 r270 bottom
C146 "EMK212BJ106KG-T" 0805L 7726,1262 r270 top
C147 "06033C104JAT2A" 0603L#1 7785,1262 r270 top
C148 "06033C104JAT2A" 0603L#1 7886.27,1394 r270 top
C149 "06035A331JAT2A" 0603L#1 7100,2065 r270 top
C150 "C1608X5R1A106M" 0603L#1 7097,2150 r180 top
C151 "06033C104JAT2A" 0603L#1 7199.13,2150 r0 top
C152 "C1608X5R1A106M" 0603L#1 7004,1890 r0 top
C153 "06033C104JAT2A" 0603L#1 5974,1940 r180 top
C154 "06035A100JAT2A" 0603L#1 7866.44,1044 r180 top
C155 "C1608X5R1C105K" 0603L#1 7975,1044 r0 top
C156 "GRM31CR60J476ME19L" 1206L 8094,1658.75 r180 top
C157 "GRM31CR60J476ME19L" 1206L 8094,1658.75 r180 bottom
C158 "C1608X5R1A106M" 0603L#1 8097.94,1802 r180 bottom
C159 "06033C104JAT2A" 0603L#1 8097.94,1802 r180 top
C160 "C0603C475K8PACTU" 0603L#1 7364.49,2090 r180 bottom
C161 "06031C103MAT2A" 0603L#1 7364.49,1940 r180 bottom
C162 "GRM188R71E332KA01D" 0603L#1 8079,1109.54 r0 top
C163 "C1608X5R1A106M" 0603L#1 5974,1940 r180 bottom
C164 "06033C104JAT2A" 0603L#1 6026,2345.06 r90 top
C165 "C1608X5R1A106M" 0603L#1 6026,2345.06 r90 bottom
C166 "C1608X5R1A106M" 0603L#1 6309,2150 r180 top
C167 "06033C104JAT2A" 0603L#1 6949,1319.27 r270 top
C168 "C1608X7R1C224K" 0603L#1 6925,1716 r90 top
C169 "GRM155R60J104KA01D" 0402L#1 7022.74,1361 r270 top
C170 "GRM155R60J104KA01D" 0402L#1 6875.26,1361 r90 top
C171 "C1608X5R1A106M" 0603L#1 5954,2215 r90 bottom
C172 "C1608X5R1A106M" 0603L#1 6494.67,2437 r90 top
C173 "EMK212BJ106KG-T" 0805L 6908.5,1319.27 r270 bottom
C174 "GRM188R71C273KA01D" 0603L#1 7117,1716 r90 top
C175 "GRM188R71C273KA01D" 0603L#1 6781,1716 r270 top
C176 "06033C104JAT2A" 0603L#1 6393.41,1084 r0 top
C177 "06033C104JAT2A" 0603L#1 5807.44,2341.5 r180 top
C178 "06033C393KAT2A" 0603L#1 7021,1716 r90 top
C179 "06033C393KAT2A" 0603L#1 6877,1716 r90 top
C180 "GRM31CR61A226ME19L" 1206L 7527,1283 r180 top
C181 "GRM31CR61A226ME19L" 1206L 7527,1283 r180 bottom
C182 "GRM31CR61A226ME19L" 1206L 6419,1283 r0 top
C183 "GRM31CR61A226ME19L" 1206L 6419,1283 r0 bottom
C184 "EMK212BJ106KG-T" 0805L 6989.5,1319.27 r270 bottom
C185 "06033C104JAT2A" 0603L#1 6202.68,2418 r270 top
C186 "C1608X5R1A106M" 0603L#1 6494.68,2539 r270 top
C187 "06035A561JAT2A" 0603L#1 6301.68,2558.87 r270 bottom
C188 "C1608X5R1A106M" 0603L#1 5746,2406.01 r180 top
C189 "06033C104JAT2A" 0603L#1 5950.56,2341.5 r0 top
C190 "C1608X5R1A106M" 0603L#1 6393.41,1084 r0 bottom
C191 "06033C104JAT2A" 0603L#1 7547.5,2513.93 r270 top
C192 "GRM188R71C472KA01D" 0603L#1 7243,2536.39 r90 top
C193 "TPSB476K010R0250" 3528-21#2 2229,87.12 r270 bottom
C194 "C1608X5R1A106M" 0603L#1 2397.5,84.38 r270 bottom
C195 "C1608X5R1A106M" 0603L#1 6202.68,2418 r270 bottom
C196 "C1608X5R1A106M" 0603L#1 7243,2402.53 r90 top
C197 "C1608X5R1A106M" 0603L#1 5950.56,2292.5 r0 top
C198 "06033C104JAT2A" 0603L#1 7291,2536.39 r90 top
C199 "06033C104JAT2A" 0603L#1 7552.59,1084 r180 top
C200 "C1608X5R1A106M" 0603L#1 6118.26,789.7 r0 top
C201 "C1608X5R1C105K" 0603L#1 329.24,689.56 r270 bottom
C202 "C1608X5R1A106M" 0603L#1 7547.5,2513.93 r270 bottom
C203 "C1608X5R1A106M" 0603L#1 7552.59,1084 r180 bottom
C204 "C1608X5R1A106M" 0603L#1 7291,2536.39 r90 bottom
C205 "C1608X5R1A105K" 0603L#1 6142,567 r90 bottom
C206 "C1005X5R1A104K" 0402L#1 4365.2,2316.76 r270 bottom
C207 "C1005X5R1A104K" 0402L#1 4247.09,2316.76 r270 bottom
C208 "C1005X5R1A104K" 0402L#1 4188.03,2316.76 r270 bottom
C209 "C1005X5R1A104K" 0402L#1 4089.61,2316.76 r270 bottom
C210 "0603YC104JAT2A" 0603L#1 111.3,839 r0 bottom
C211 "C1608X5R1C105K" 0603L#1 228.7,775.86 r0 bottom
C212 "GRM31CR60J107ME39L" 1206 6027,846 r0 bottom
C213 "06033C104JAT2A" 0603L#1 6060,407.69 r270 bottom
C214 "C0603X5R0J104K" 0201#1 6034.59,781.24 r180 top
C215 "GRM155R71A104KA01D" 0402L#1 4592,1726 r180 top
C216 "GRM155R71A104KA01D" 0402L#1 4935,1842 r0 top
C217 "GRM155R71A104KA01D" 0402L#1 6144.55,1790 r180 top
C218 "GRM155R71A104KA01D" 0402L#1 5629,1040 r180 top
C219 "GRM155R71A104KA01D" 0402L#1 6302.85,1090 r180 top
C220 "GRM155R71A104KA01D" 0402L#1 6567,990 r0 bottom
C221 "GRM155R71A104KA01D" 0402L#1 6482,1090 r0 bottom
C222 "GRM155R71A104KA01D" 0402L#1 7648,1090 r0 top
C223 "GRM155R71A104KA01D" 0402L#1 7220,1090 r180 bottom
C224 "GRM155R71A104KA01D" 0402L#1 6298,1790 r180 bottom
C225 "GRM155R71A104KA01D" 0402L#1 6482,1790 r0 bottom
C226 "GRM155R71A104KA01D" 0402L#1 7436,1790 r0 bottom
C227 "GRM155R71A104KA01D" 0402L#1 7220,1790 r180 bottom
C228 "500R07S0R5BV4T" 0402L#1 3602.85,1696.45 r270 bottom
C229 "500R07S0R5BV4T" 0402L#1 3602.85,1623.46 r90 bottom
C230 "GRM1885C1H470JA01D" 0603L#1 5705.33,1739.79 r270 bottom
C231 "C1005X5R1A104K" 0402L#1 5668.33,1740.79 r90 bottom
C232 "C1005X5R0J105M" 0402L#1 5638.33,1740.79 r270 bottom
C233 "GRM1555C1H4R7CA01D" 0402L#1 5608.33,1740.79 r270 bottom
C234 "GRM1885C1H470JA01D" 0603L#2 5705.33,1739.79 r270 top
C235 "C1005X5R1A104K" 0402L#1 5668.33,1740.79 r90 top
C236 "C1005X5R0J105M" 0402L#1 5638.33,1740.79 r270 top
C237 "GRM1555C1H4R7CA01D" 0402L#1 5608.33,1740.79 r270 top
C238 "GRM1555C1H4R7CA01D" 0402L#1 5512.24,1614.68 r0 top
C239 "GRM155R71E103KA01D" 0402L#1 5512.24,1584.68 r0 top
C240 "C1005X5R0J105M" 0402L#1 5512.24,1554.68 r0 top
C241 "GRM1555C1H4R7CA01D" 0402L#1 5434.24,1614.68 r180 top
C242 "GRM155R71E103KA01D" 0402L#1 5434.24,1584.68 r180 top
C243 "C1005X5R0J105M" 0402L#1 5434.24,1554.68 r180 top
C244 "GRM1555C1H561JA01D" 0402L#1 5662.29,1619.31 r180 top
C245 "GRM1555C1H470JA01D" 0402L#1 5662.29,1658.68 r180 top
C246 "GRM1555C1H4R7CA01D" 0402L#1 5622.92,1547.31 r180 top
C247 "GRM1555C1H2R2CA01D" 0402L#2 5622.92,1443 r180 top
C248 "GRM1555C1H4R7CA01D" 0402L#1 5377.02,1616 r270 top
C249 "GRM1555C1H220JA01D" 0402L#1 5603.33,1813.69 r0 top
C250 "C1005X5R1A104K" 0402L#1 5433,2179.37 r0 top
C251 "C1005X5R1A104K" 0402L#1 5603.33,1844 r0 top
C252 "C1005X5R0J105M" 0402L#1 5501.43,1989.09 r0 top
C253 "GRM155R71E103KA01D" 0402L#1 5501.43,1959.09 r0 top
C254 "GRM1555C1H270JA01D" 0402L#1 5501.43,1929.09 r0 top
C255 "C1005X5R0J105M" 0402L#1 5351.04,1989.09 r180 top
C256 "GRM155R71E103KA01D" 0402L#1 5351.04,1959.09 r180 top
C257 "GRM1555C1H270JA01D" 0402L#1 5351.04,1929.09 r180 top
C258 "C1005X5R1A104K" 0402L#1 4743.16,1544.09 r0 top
C259 "C1005X5R1A104K" 0402L#1 4410.91,2564.56 r270 top
C260 "C1005X5R1A104K" 0402L#3 4226,2537.87 r0 bottom
C261 "GRM155R71A104KA01D" 0402L#1 8338,1790 r0 top
C262 "GRM033R61A472KA01D" 0201#2 3927.57,1441.46 r270 top
C263 "GRM033R61A472KA01D" 0201#2 3927.57,1494.45 r90 top
C264 "LLL185R71E103MA01L" 0306 3180.8,1216.52 r90 top
C265 "LLL185R71E103MA01L" 0306 3273.64,1216.52 r270 top
C266 "LLL185R71H222MA01L" 0306 3180.8,1216.52 r270 bottom
C267 "LLL185R71H222MA01L" 0306 3273.64,1216.52 r90 bottom
C268 "LLL185R71H222MA01L" 0306 3180.8,1443.79 r90 bottom
C269 "LLL185R71H222MA01L" 0306 3273.64,1443.79 r270 bottom
C270 "LLL185R71E103MA01L" 0306 3180.8,1443.79 r270 top
C271 "LLL185R71E103MA01L" 0306 3273.64,1443.79 r90 top
C272 "C1005X7R1E103K" 0402L#1 3246.91,1160 r180 bottom
C273 "C1005X5R1A104K" 0402L#1 3227.22,1284.88 r180 top
C274 "C1005X5R1A104K" 0402L#1 3227.22,1375.43 r180 top
C275 "TPSA106K010R0900" 3216-18 3251.22,1025 r180 top
C276 "C1608X5R1A106M" 0603L#1 3328.3,670 r0 bottom
C277 "06033C104JAT2A" 0603L#1 3328.3,670 r0 top
C278 "06031C103MAT2A" 0603L#3 3444,790.69 r270 top
C279 "C0603C150J5GACTU" 0603L#1 3328.3,921 r0 top
C280 "C1608X5R1A106M" 0603L#1 3021.57,979.41 r270 bottom
C281 "06033C104JAT2A" 0603L#1 3021.57,979.41 r270 top
C282 "C1608X5R1A106M" 0603L#1 2940.99,792.02 r270 top
C283 "06033C104JAT2A" 0603L#1 2896.99,792.02 r270 top
C284 "C1608X5R0J226M080AC" 0603L#1 2804.99,701.02 r0 top
C285 "C1608X5R0J226M080AC" 0603L#1 2906.99,701.02 r180 top
C286 "GRM1555C1H100JA01D" 0402L#1 2962.99,932.02 r90 top
C287 "GRM188R61A225KE34D" 0603L#1 2665,666.32 r90 bottom
C288 "06033C104JAT2A" 0603L#1 2665,666.32 r90 top
C289 "C1608X5R1A106M" 0603L#1 2533.47,918.46 r270 top
C290 "06033C104JAT2A" 0603L#1 2533.47,918.46 r270 bottom
C291 "GRM1555C1H1R0CA01D" 0402L#1 3777,1314.47 r0 bottom
C292 "GRM1555C1H1R0CA01D" 0402L#1 3777,1345.84 r180 bottom
C293 "GRM1555C1H2R4CA01D" 0402L#1 3836,1293.16 r90 bottom
C294 "GRM1555C1H2R4CA01D" 0402L#1 3836,1367.16 r90 bottom
C295 "C1005X5R1A104K" 0402L#1 3024.02,1263 r90 bottom
C296 "C1005X5R1A104K" 0402L#1 3024.02,1397.31 r270 bottom
C297 "C1608X5R1A106M" 0603L#1 3250,790.68 r270 bottom
C298 "06033C104JAT2A" 0603L#1 3250,790.68 r270 top
C299 "C1608X5R1A106M" 0603L#1 2481,655.68 r270 bottom
C300 "06033C104JAT2A" 0603L#1 2481,655.68 r270 top
C301 "LLL185R71E103MA01L" 0306 3492.62,1212.6 r90 top
C302 "LLL185R71E103MA01L" 0306 3619.15,1212.59 r270 top
C303 "LLL185R71H222MA01L" 0306 3492.62,1212.59 r270 bottom
C304 "LLL185R71H222MA01L" 0306 3619.15,1212.59 r90 bottom
C305 "LLL185R71H222MA01L" 0306 3492.62,1447.72 r90 bottom
C306 "LLL185R71H222MA01L" 0306 3619.15,1447.72 r270 bottom
C307 "LLL185R71E103MA01L" 0306 3492.62,1447.72 r270 top
C308 "LLL185R71E103MA01L" 0306 3619.15,1447.72 r90 top
C309 "C1005X7R1E103K" 0402L#1 3592.3,1525 r180 bottom
C310 "C1005X5R1A104K" 0402L#1 3844.12,1097.2 r270 top
C311 "C1005X7R1C103K" 0402L#1 697,1805 r0 top
C312 "C1005X7R1C103K" 0402L#1 697,2105 r0 top
C313 "C1005X7R1C103K" 0402L#1 2009,2405 r0 top
C314 "C1005X7R1C103K" 0402L#1 2386,2405 r0 top
C315 "C1005X7R1C103K" 0402L#1 1161,2105 r0 top
C316 "C1005X7R1C103K" 0402L#1 1538,2105 r0 top
C317 "C1005X7R1C103K" 0402L#1 1161,2405 r0 top
C318 "C1005X7R1C103K" 0402L#1 1538,2405 r0 top
C319 "C1005X7R1C103K" 0402L#1 2009,2105 r0 top
C320 "C1005X7R1C103K" 0402L#1 2387,2105 r0 top
C321 "C1005X5R1A104K" 0402L#1 697,1773.13 r0 top
C322 "C1005X5R1A104K" 0402L#1 697,2073.13 r0 top
C323 "C1005X5R1A104K" 0402L#1 2009,2373.13 r0 top
C324 "C1005X5R1A104K" 0402L#1 2386,2373.13 r0 top
C325 "C1005X5R1A104K" 0402L#1 1161,2073.13 r0 top
C326 "C1005X5R1A104K" 0402L#1 1538,2073.13 r0 top
C327 "C1005X5R1A104K" 0402L#1 1161,2373.13 r0 top
C328 "C1005X5R1A104K" 0402L#1 1538,2373.13 r0 top
C329 "C1005X5R1A104K" 0402L#1 2009,2073.13 r0 top
C330 "C1005X5R1A104K" 0402L#1 2387,2073.13 r0 top
C331 "C1005X5R1A104K" 0402L#1 558,1900 r270 bottom
C332 "C1005X5R1A104K" 0402L#1 558,2200 r270 bottom
C333 "C1005X5R1A104K" 0402L#1 1870,2500 r270 bottom
C334 "C1005X5R1A104K" 0402L#1 2247,2500 r270 bottom
C335 "C1005X5R1A104K" 0402L#1 1022,2200 r270 bottom
C336 "C1005X5R1A104K" 0402L#1 1399,2200 r270 bottom
C337 "C1005X5R1A104K" 0402L#1 1022,2500 r270 bottom
C338 "C1005X5R1A104K" 0402L#1 1399,2500 r270 bottom
C339 "C1005X5R1A104K" 0402L#1 1870,2200 r270 bottom
C340 "C1005X5R1A104K" 0402L#1 2247,2200 r270 bottom
C341 "C1005C0G1E102J" 0402L#1 2199.64,2636 r180 bottom
C342 "C1005C0G1E102J" 0402L#1 1351.64,2336 r180 bottom
C343 "C1005C0G1E102J" 0402L#1 1351.64,2636 r180 bottom
C344 "C1005C0G1E102J" 0402L#1 1866,2336 r180 bottom
C345 "C1005C0G1E102J" 0402L#1 2199.64,2336 r180 bottom
C346 "C1005X5R1A104K" 0402L#1 1519.06,1785.91 r90 bottom
C347 "C1005X5R1A104K" 0402L#1 1147,1746.84 r180 top
C349 "C1005X5R1A104K" 0402L#1 2323,1746.84 r180 top
C350 "C1005X5R1A104K" 0402L#1 446.68,1591.32 r270 bottom
C351 "C1005X5R1A104K" 0402L#1 265,1335.47 r270 bottom
C352 "C1005X5R1A104K" 0402L#1 465,1175.16 r180 bottom
C353 "C1005X5R1A104K" 0402L#1 273,1694 r0 bottom
C354 "C1005X5R1A104K" 0402L#1 405,1591.32 r270 bottom
C355 "C1005X5R1A104K" 0402L#1 1698.48,2410 r90 top
C356 "GRM188R61A225KE34D" 0603L#1 66,1912.57 r270 bottom
C357 "06033C104JAT2A" 0603L#1 66,1912.57 r270 top
C358 "C1608X5R1A106M" 0603L#1 250,1923.2 r90 bottom
C359 "06033C104JAT2A" 0603L#1 250,1923.2 r90 top
C360 "293D105X0016A2TE3" 3216-18 495,1900 r90 bottom
C361 "293D105X0016A2TE3" 3216-18 495,2200 r90 bottom
C362 "293D105X0016A2TE3" 3216-18 1807,2500 r90 bottom
C363 "293D105X0016A2TE3" 3216-18 2184,2500 r90 bottom
C364 "293D105X0016A2TE3" 3216-18 959,2200 r90 bottom
C365 "293D105X0016A2TE3" 3216-18 1336,2200 r90 bottom
C366 "293D105X0016A2TE3" 3216-18 959,2500 r90 bottom
C367 "293D105X0016A2TE3" 3216-18 1336,2500 r90 bottom
C368 "293D105X0016A2TE3" 3216-18 1807,2200 r90 bottom
C369 "293D105X0016A2TE3" 3216-18 2184,2200 r90 bottom
C370 "Used in BOM report" 0402L#1 1743,1170.84 r270 bottom
C371 "Used in BOM report" 0402L#1 1833,1185.31 r180 bottom
C372 "Used in BOM report" 0402L#1 1923,1170.84 r270 bottom
C373 "Used in BOM report" 0402L#1 1743,1257.65 r270 bottom
C374 "Used in BOM report" 0402L#1 1833,1272.12 r180 bottom
C375 "Used in BOM report" 0402L#1 1923,1257.65 r270 bottom
C376 "Used in BOM report" 0402L#1 1743,1402.66 r270 bottom
C377 "Used in BOM report" 0402L#1 1833,1388.19 r180 bottom
C378 "Used in BOM report" 0402L#1 1923,1402.66 r270 bottom
C379 "Used in BOM report" 0402L#1 1743,1489.47 r90 bottom
C380 "Used in BOM report" 0402L#1 1833,1475 r180 bottom
C381 "Used in BOM report" 0402L#1 1923,1489.47 r90 bottom
C382 "EMK212BJ106KG-T" 0805L 1870,900 r270 bottom
C383 "EMK212BJ106KG-T" 0805L 1870,900 r270 top
C384 "C1005X5R1A104K" 0402L#1 1603.02,1015 r180 top
C385 "GRM1555C1H100JA01D" 0402L#1 1517.37,1065.02 r0 top
C386 "C2012X5R1C226K125AC" 0805L 1514,900 r90 top
C387 "C2012X5R1C226K125AC" 0805L 1444,900 r90 top
C388 "C2012X5R1C226K125AC" 0805L 1444,900 r90 bottom
C389 "GRM188R61A225KE34D" 0603L#1 368.58,2099 r180 bottom
C390 "06033C104JAT2A" 0603L#1 368.58,2099 r180 top
C391 "C1608X5R1A106M" 0603L#1 154.56,2286 r0 bottom
C392 "06033C104JAT2A" 0603L#1 154.56,2286 r0 top
C393 "06033C104JAT2A" 0603L#1 185,2191 r90 top
C394 "C2012X5R1C226K125AC" 0805L 1005.53,684.17 r180 top
C395 "C1608X5R1A106M" 0603L#1 1003.56,995 r0 bottom
C396 "06033C104JAT2A" 0603L#1 1003.56,995 r0 top
C397 "C2012X5R1C226K125AC" 0805L 1305.53,684.17 r180 top
C398 "C1608X5R1A106M" 0603L#1 1303.56,995 r0 bottom
C399 "06033C104JAT2A" 0603L#1 1303.56,995 r0 top
C400 "C2012X5R1C226K125AC" 0805L 1155.53,684.17 r180 top
C401 "C1608X5R1A106M" 0603L#1 1153.56,995 r0 bottom
C402 "06033C104JAT2A" 0603L#1 1153.56,995 r0 top
C403 "Used in BOM report" 0402L#1 1478,1018 r180 top
C404 "C1608X5R1A106M" 0603L#1 328,1923.2 r90 bottom
C405 "06033C104JAT2A" 0603L#1 328,1923.2 r90 top
C406 "C1608X5R1A106M" 0603L#1 804.89,934.3 r90 bottom
C407 "06033C104JAT2A" 0603L#1 804.89,934.3 r90 top
C408 "06031C103MAT2A" 0603L#1 670.42,1050 r0 top
C409 "C0603C220J5GACTU" 0603L#1 541.11,934.3 r90 top
C410 "C1608X5R1A106M" 0603L#1 683.32,856 r0 bottom
C411 "06033C104JAT2A" 0603L#1 683.32,856 r0 top
C413 "293D105X0016A2TE3" 3216-18 247.33,1621 r270 top
C414 "293D105X0016A2TE3" 3216-18 342,1621 r270 top
C415 "C1608X5R1A106M" 0603L#1 2251.99,792.02 r270 top
C416 "06033C104JAT2A" 0603L#1 2207.99,792.02 r270 top
C417 "GRM1555C1H100JA01D" 0402L#1 2273.99,932.02 r90 top
C418 "C1608X5R0J226M080AC" 0603L#1 2111.18,701.02 r0 top
C419 "C1608X5R0J226M080AC" 0603L#1 2222.8,701.02 r180 top
D1 "PMEG3005EL,315" SOD882 2855.99,798.02 r270 top
D2 "1N4148W-7-F" SOD-123 5711.48,1165 r180 bottom
D3 "D-MMBD352WT1" SOT-23 484.68,1065 r180 bottom
D4 "1N4148W-7-F" SOD-123 5711.48,1115 r180 top
D5 "MBRS540T3G" SMC 7193,1191 r0 top
D6 "MBRS540T3G" SMC 6705,1191 r180 top
D7 "PMEG3005EL,315" SOD882 2166.99,798.02 r270 top
DC "RS-032G05A3-SM RT" SW_RS-032G05A3-SM 650,1900 r180 top
"DC COUPLED" "LTST-C190GKT" LED_LTST-C190 4039,275 r90 top
DEVCLK "SASF546-P26-X1" CONN_LTI_SASF546-P26-X1 3500.06,2322 r0 top
DPDT_1A "TESTPOINT" TP_VIA_060RND040 882.48,1998.51 r180 top
DPDT_1B "TESTPOINT" TP_VIA_060RND040 882.48,2100 r180 top
DPDT_2A "TESTPOINT" TP_VIA_060RND040 2119.48,2320 r180 top
DPDT_2B "TESTPOINT" TP_VIA_060RND040 2119.48,2620 r180 top
DPDT_3A "TESTPOINT" TP_VIA_060RND040 1271.48,2620 r180 top
DPDT_3B "TESTPOINT" TP_VIA_060RND040 1271.48,2320 r180 top
DPDT_4A "TESTPOINT" TP_VIA_060RND040 1606,2320 r180 top
DPDT_4B "TESTPOINT" TP_VIA_060RND040 1606,2500 r180 top
DPDT_5A "TESTPOINT" TP_VIA_060RND040 2454,2620 r180 top
DPDT_5B "TESTPOINT" TP_VIA_060RND040 2454,2320 r180 top
EXT5V_FMC12V "PBC03SAAN" PBC03SAAN 7840,90 r0 top
EXT_Vcmo "TSW-102-07-G-S" TSW-102-07-G-S 3701.78,727 r90 top
EXT_VCO "SASF546-P26-X1" CONN_LTI_SASF546-P26-X1 5316.02,1040 r270 top
F1 "1206SFF200F/63-2" 1206 1948,185.3 r180 bottom
FID1 "Fiducial" Fiducial10-30 88,2592 r0 top
FID2 "Fiducial" Fiducial10-30 88,478 r0 top
FID3 "Fiducial" Fiducial10-30 8745,2592 r0 top
FL1 "NFM41PC204F1H3L" FIL_NFM41P 976,845 r90 top
FL2 "NFM41PC204F1H3L" FIL_NFM41P 1126,845 r90 top
FL3 "NFM41PC204F1H3L" FIL_NFM41P 1276,845 r90 top
FMC_RX1 "ASP-134488-01" CONN_SEARAY_ASP-134488-01 8513,1341.94 r90 bottom locked
FTDI_3P3V "TSW-103-07-G-S" TSW-103-07-G-S 4711.28,426 r180 top
GND "5011" Keystone5011 3744,1795 r0 top
GND1 "5011" Keystone5011 5685,2576 r0 top
GND2 "5011" Keystone5011 8142,95 r0 top
GND3 "5011" Keystone5011 7741,2526 r0 top
GND4 "TESTPOINT" TP_VIA_060RND040 1774,94.49 r90 top
H3 "1648-440-AL" Keystone_1902C 566,580 r180 bottom
H4 "1648-440-AL" Keystone_1902C 334,2505 r180 bottom
H5 "NY PMS 440 0025 PH" "NY PMS 440 0025 PH"#1 566,580 r0 top
H6 "NY PMS 440 0025 PH" "NY PMS 440 0025 PH"#2 334,2505 r0 top
J1 "TSW-104-07-G-S" TSW-104-07-G-S 7046,690 r270 top
J2 "TSW-102-07-G-S" TSW-102-07-G-S 5826,1415 r180 top
J3 "TSW-102-07-G-S" TSW-102-07-G-S 6495,690 r90 top
K1 "RF180-5" Relay_RF180 465,1330.16 r270 top
K1_Ax "TESTPOINT" TP_VIA_060RND040 735,1615 r90 top
K1_Bx "TESTPOINT" TP_VIA_060RND040 835,1615 r90 top
K2 "RF180-5" Relay_RF180 1035,1330.16 r90 top
K2_Ax "TESTPOINT" TP_VIA_060RND040 935,1615 r180 top
K2_Bx "TESTPOINT" TP_VIA_060RND040 1035,1615 r180 top
K3 "RF180-5" Relay_RF180 1543,1330.16 r270 top
K3_Ax "TESTPOINT" TP_VIA_060RND040 1147,1615 r180 top
K3_Bx "TESTPOINT" TP_VIA_060RND040 1973,1615 r0 top
K4 "RF180-5" Relay_RF180 2123,1330.16 r270 top
K4_Ax "TESTPOINT" TP_VIA_060RND040 2073,1615 r0 top
K4_Bx "TESTPOINT" TP_VIA_060RND040 2223,1615 r0 top
K5 "RF180-5" Relay_RF180 2693,1330.16 r90 top
K5_Ax "TESTPOINT" TP_VIA_060RND040 2473,1615 r270 top
K5_Bx "TESTPOINT" TP_VIA_060RND040 2323,1615 r0 top
K6 "DS1E-SL2-DC5V" RELAY_DS1E-SL2 2739,226 r270 bottom
K7 "DS1E-SL2-DC5V" RELAY_DS1E-SL2 3364,226 r270 bottom
K8 "DS1E-SL2-DC5V" RELAY_DS1E-SL2 3989,226 r270 bottom
"KC705 JTAG" "TSW-102-07-G-S" TSW-102-07-G-S 8004,915 r180 top
L1 "BLM15HG102SN1D" 0402L#1 5104.36,1790 r0 bottom
L2 "BLM18SG331TN1D" 0603 4436.42,1932.5 r180 bottom
L3 "BLM18SG331TN1D" 0603 4233.46,2396.5 r0 bottom
L4 "BLM18SG331TN1D" 0603 4467.92,2035.92 r90 bottom
L5 "BLM18SG331TN1D" 0603 4128.98,2428 r270 bottom
L6 "BLM18SG260TN1D" 0603 6914,1908 r270 top
L7 "BLM18SG121TN1D" 0603 8094,1739.21 r0 top
L8 "CDRH6D28NP-3R0NC" CDRH6D28 7843,1614 r90 top
L9 "BLM18SG260TN1D" 0603 6094.5,1940 r180 top
L10 "BLM18SG260TN1D" 0603 6026,2134.5 r90 top
L11 "MSS1038-702NLB" MSS1038 7413,1571 r180 top
L12 "744325550" WE-HC6 6462,1571 r180 top
L13 "BLM18SG260TN1D" 0603 5954,2071.5 r90 top
L14 "BLM18SG121TN1D" 0603 6365.85,1175 r270 top
L15 "BLM18SG260TN1D" 0603 5835,2437.5 r270 top
L16 "BLM18SG260TN1D" 0603 5923,2437.5 r270 top
L17 "BLM18SG260TN1D" 0603 2366,171.39 r0 bottom
L18 "BLM18SG260TN1D" 0603 7511,2602.93 r0 top
L19 "BLM18SG331TN1D" 0603 4467.92,2218.71 r270 bottom
L20 "BLM18SG121TN1D" 0603 7580.15,1175 r270 top
L21 "BLM18SG331TN1D" 0603 3969.5,2247.39 r270 bottom
L22 "BLM18SG331TN1D" 0603 3969.5,2030.86 r270 bottom
L23 "BLM18SG331TN1D" 0603 6260,251 r0 top
L24 "BLM18SG121TN1D" 0603 5753,491 r180 bottom
L25 "BLM18SG121TN1D" 0603L#1 5692.56,682 r270 bottom
L26 "BLM18SG260TN1D" 0603 115.24,775.86 r180 bottom
L27 "BLM15HG102SN1D" 0402L#1 5743,1710.99 r90 bottom
L28 "BLM15HG102SN1D" 0402L#4 5761.84,1733.13 r180 top
L29 "BLM15HG102SN1D" 0402L#1 5492.55,1502.68 r90 top
L30 "BLM15HG102SN1D" 0402L#1 5453.92,1502.68 r90 top
L31 "BLM15HG102SN1D" 0402L#1 5976,1415 r180 top
L32 "BLM15HG102SN1D" 0402L#1 5501.43,2019.09 r180 top
L33 "BLM15HG102SN1D" 0402L#1 5351.04,2019.09 r0 top
L34 "BLM15HG102SN1D" 0402L#1 5178,1620.82 r180 bottom
L35 "BLM18SG121TN1D" 0603 3208.81,670 r0 top
L36 "BLM18SG121TN1D" 0603 3013.5,791.09 r90 top
L37 "VLS2012ET-6R8M" VLS2012 2766.49,788.82 r270 top
L38 "LQW18AN5N6D10D" LQW18A 3777,1273.01 r0 bottom
L39 "LQW18AN5N6D10D" LQW18A 3777,1387.3 r0 bottom
L40 "BLM18SG121TN1D" 0603 2324.5,791.09 r90 top
L41 "VLS2012ET-6R8M" VLS2012 2077.49,788.82 r270 top
L42 "BLM18SG121TN1D" 0603 2824.49,638.76 r180 top
L43 "BLM18SG121TN1D" 0603 3082.01,975.47 r90 top
L44 "BLM18SG121TN1D" 0603 2475.01,914.52 r90 top
L45 "BLM18SG121TN1D" 0603 3244.01,912.48 r270 top
L46 "BLM18SG121TN1D" 0603 2475.01,777.48 r270 top
L47 "BLM18SG121TN1D" 0603 66,2032.06 r270 top
L48 "BLM18SG121TN1D" 0603 255.99,1801.41 r90 top
L49 "XFL4020-102MEB" XFL4020 1692,674 r180 top
L50 "BLM18SG121TN1D" 0603 396,2008 r90 top
L51 "BLM18SG121TN1D" 0603 127,2194.94 r90 top
L52 "BLM18SG121TN1D" 0603 328,1801.41 r90 top
L53 "BLM18SG121TN1D" 0603 836.39,846.31 r180 top
L54 "BLM18SG121TN1D" 0603 561.52,850.01 r0 top
L55 "0603HC-3N9XJLU" 0603HC 3894,1296.47 r0 bottom
L56 "0603HC-3N9XJLU" 0603HC 3894,1363.84 r0 bottom
LD "LTST-C190GKT" LED_LTST-C190 5423.16,2235.37 r180 top
LD1 "TESTPOINT" TESTPOINT#1 4681.93,2181 r270 top
LD2 "TESTPOINT" TESTPOINT#1 3818,2561 r180 top
LF1 "C1608C0G1E392J" 0603L#1 4049.3,2436.74 r180 top
LF2 "06035A470JAT2A" 0603L#1 4049.3,2386.74 r180 top
LF3 "RC0603FR-07619RL" 0603L#1 3969.86,2409.18 r90 top
LF7 "ACM7060-301-2PL-TL" IND_TDK_ACM7060 1547.5,153.54 r0 bottom
LMK_INT "TSW-102-07-G-S" TSW-102-07-G-S 6739,2040 r180 top
LMK_LDO "TSW-102-07-G-S" TSW-102-07-G-S 6176,2040 r180 top
LMKCLK "SASF546-P26-X1" CONN_LTI_SASF546-P26-X1 4611.5,2482.51 r0 top
LMX_INT "TSW-102-07-G-S" TSW-102-07-G-S 7527,2040 r180 top
LMX_LDO "TSW-102-07-G-S" TSW-102-07-G-S 6964,2040 r180 top
LO2_N "TESTPOINT" TESTPOINT#2 5173.05,1833.99 r90 top
LO2_P "TESTPOINT" TESTPOINT#2 5173.05,1796.01 r90 top
LO3_N "TESTPOINT" TESTPOINT#2 5223.32,1728 r90 top
LO3_P "TESTPOINT" TESTPOINT#2 5186.69,1728 r90 top
Logo1 "ESD Susceptible" ESD_Overlay_Small 7948,1930 r0 top
Logo2 "Texas Instruments" TI_Symbol_Overlay_Small 7734,2277 r0 top
Logo3 "Pb-Free Symbol" Pb-Free_Overlay_Small 7807,2062 r0 top
Logo4 "FCC disclaimer" FCC_disclaimer 8612,1559 r90 top
LOGO5 "CAUTION HOT SURFACE" IEC_HotSurface_Small 4842,1340 r180 bottom
NCO "TSW-103-07-G-D" TSW-103-07-G-D 4965.5,1140 r0 top
OFFSET "TESTPOINT" TP_VIA_060RND040 501,1611 r90 top
"OFFSET ADJ" "3214W-1-102E" TRIM_3214W 112,1623 r0 top
OR "TSW-103-07-G-S" TSW-103-07-G-S 4649.5,2015 r180 top
OR_T0 "LTST-C190KFKT" LED_LTST-C190 6107,1232.52 r0 top
OR_T1 "LTST-C190KFKT" LED_LTST-C190 6107,1090 r0 top
OSCin "SASF546-P26-X1" CONN_LTI_SASF546-P26-X1 5693.24,2125 r0 top
PG_RX1 "TSW-102-07-G-S" TSW-102-07-G-S 8038,2559 r180 top
Q1 "CSD18532Q5B" TRANS_NexFET_Q5B 1914,143.22 r180 top
Q2 "FDY1002PZ" SOT-563 2070,1856.39 r0 top
Q3 "FDY1002PZ" SOT-563 1782,1856.39 r0 top
Q4 "FDY1002PZ" SOT-563 1926,1856.39 r0 top
R1 "CRCW04028K06FKED" 0402L#1 5990,1140 r0 bottom
R2 "CRCW04021K20JNED" 0402L#1 6136.53,1212.84 r270 bottom
R3 "CRCW04021M00JNED" 0402L#1 5881,1254.36 r0 bottom
R4 "CRCW060310K0FKEA" 0603L#1 5512.5,1090 r180 top
R5 "CRCW060310K0FKEA" 0603L#1 4965.5,1004 r90 bottom
R6 "CRCW060310K0FKEA" 0603L#1 4865.5,1004 r90 bottom
R7 "ERJ-1GE0R00C" 0201#1 4677.2,1224.93 r90 bottom
R8 "ERJ-1GE0R00C" 0201#1 4587.2,1165.87 r90 bottom
R9 "ERJ-1GE0R00C" 0201#1 4358.85,1010.18 r0 bottom
R10 "CRCW04021K20JNED" 0402L#1 6136.53,1109.68 r90 bottom
R11 "CRCW04021M00JNED" 0402L#1 5836.31,950 r0 top
R12 "CRCW04021K33FKED" 0402L#1 5911.31,1122 r0 bottom
R13 "RG1608P-332-B-T5" 0603L#1 4030.26,1175 r180 top
R14 "CRCW060310K0FKEA" 0603L#1 4825.28,858.81 r0 top
R15 "CRCW060310K0FKEA" 0603L#1 4825.28,811.41 r0 top
R16 "CRCW060310K0FKEA" 0603L#1 4825.28,763.41 r0 top
R17 "RC0603JR-07750RL" 0603L#1 4825.28,763.41 r0 bottom
R18 "ERJ-1GE0R00C" 0201#1 4174.99,1694 r90 bottom
R19 "ERJ-1GE0R00C" 0201#1 4174.99,1694 r90 top
R20 "ERJ-1GE0R00C" 0201#1 4201.99,1694 r90 top
R21 "ERJ-1GE0R00C" 0201#1 4201.99,1694 r90 bottom
R22 "ERJ-1GE0R00C" 0201#1 4188,1653 r0 top
R23 "ERJ-1GE0R00C" 0201#1 4229,1666 r270 top
R24 "CRCW040210K0FKED" 0402L#1 5603.33,1879.09 r0 top
R25 "ERJ-2GE0R00X" 0402L#1 5623.02,1931.09 r270 top
R26 "ERJ-2GE0R00X" 0402L#1 6070.47,1659.68 r270 top
R27 "CRCW0402100RFKED" 0402L#1 5124.05,1939.5 r270 top
R28 "CRCW0402100RFKED" 0402L#1 5123.05,1640.5 r90 top
R29 "ERJ-2GE0R00X" 0402L#1 5020.05,1939.5 r270 top
R30 "CRCW040249R9FKED" 0402L#1 5583.65,1931.09 r90 top
R31 "RC0603JR-071K3L" 0603L#1 4825.28,811.41 r0 bottom
R32 "RC0603JR-071K3L" 0603L#1 4825.28,858.81 r0 bottom
R33 "CRCW04023K30JNED" 0402L#1 5020.05,1640.5 r90 bottom
R34 "CRCW0402100RFKED" 0402L#1 5124.05,1863.5 r90 top
R35 "CRCW0402100RFKED" 0402L#1 5123.05,1716.5 r270 top
R36 "ERJ-2GE0R00X" 0402L#1 5020.05,1863.5 r90 top
R37 "CRCW04023K30JNED" 0402L#1 5020.05,1716.5 r270 bottom
R38 "ERJ-2GE0R00X" 0402L#1 5682,1813.68 r0 top
R39 "RC0603JR-071KL" 0603L#1 6285,1940 r0 top
R40 "CSNL1206FT2L00" 1206 6176,2135.44 r180 bottom
R41 "CRCW060310K7FKEA" 0603L#1 6312,2065 r90 bottom
R42 "CSNL1206FT2L00" 1206 6739,2135.44 r180 bottom
R43 "CRCW04020000Z0ED" 0402L#1 3890.78,2106 r180 top
R44 "CRCW04020000Z0ED" 0402L#1 3890.78,2140 r180 top
R45 "CRCW0603270RJNEA" 0603L#1 3920.5,2625 r0 top
R47 "RC0603FR-072K32L" 0603L#1 4151.79,1890 r180 bottom
R48 "CRCW04020000Z0ED" 0402L#1 4375.67,2488.35 r0 top
R49 "RC0603FR-074K64L" 0603L#1 6387,2037.44 r180 bottom
R50 "Used in BOM report" 0402L#1 4298.98,2489 r180 top
R51 "CRCW040251R0JNED" 0402L#1 4432.67,2462.82 r90 top
R52 "CRCW060310R0JNEA" 0603L#1 981.8,531.69 r0 top
R53 "CRCW060310R0JNEA" 0603L#1 981.8,483.69 r0 top
R54 "CRCW0603100RJNEA" 0603L#1 7354.56,263.94 r270 bottom
R55 "CRCW0603100RJNEA" 0603L#1 7299.44,263.94 r270 bottom
R56 "CRCW0603270RJNEA" 0603L#1 4747.5,2267.95 r180 top
R57 "CRCW0603100RJNEA" 0603L#1 7299.44,487.44 r90 bottom
R58 "CRCW0603100RJNEA" 0603L#1 7354.56,466.06 r90 bottom
R59 "CRCW04020000Z0ED" 0402L#1 4507.56,2164 r0 top
R60 "CRCW04020000Z0ED" 0402L#1 4507.56,2130 r0 top
R61 "CRCW04020000Z0ED" 0402L#1 4332.98,1857 r270 top
R62 "CRCW04020000Z0ED" 0402L#1 4298.98,1857 r270 top
R63 "CRCW04020000Z0ED" 0402L#1 4096.76,1857 r270 top
R64 "CRCW04020000Z0ED" 0402L#1 4062.76,1857 r270 top
R65 "CRCW0603100RJNEA" 0603L#1 7163.68,229 r0 top
R66 "CRCW06031K00FKEA" 0603L#1 5602.47,351.73 r180 top
R67 "RC0603FR-0712KL" 0603L#1 5550.47,575.52 r270 top
R68 "CRCW0603100RJNEA" 0603L#1 6417.44,440 r180 top
R69 "CRCW0603100RJNEA" 0603L#1 6520,440 r0 bottom
R70 "RC0603JR-0710KL" 0603L#1 7820.19,1164.85 r270 bottom
R71 "RC0603JR-071KL" 0603L#1 7073,1940 r0 top
R72 "RC0603FR-0795K3L" 0603L#1 7866.44,995 r0 top
R73 "CSNL1206FT2L00" 1206 6964,2135.44 r180 bottom
R74 "CRCW060310K7FKEA" 0603L#1 7100,2065 r90 bottom
R75 "CSNL1206FT2L00" 1206 7527,1944.56 r180 bottom
R76 "CRCW060322K1FKEA" 0603L#1 7975,995 r180 top
R77 "RC0603FR-074K64L" 0603L#1 7175,2037.44 r180 bottom
R78 "RC0603FR-0710RL" 0603L#1 6973,1716 r270 top
R79 "CRCW0603732RFKEA" 0603L#1 6543.68,2539 r270 top
R80 "RC0603JR-071KL" 0603L#1 6459.66,2631 r180 top
R81 "CRCW060316K2FKEA" 0603L#1 7117,1716 r270 bottom
R82 "CRCW06037K87FKEA" 0603L#1 6781,1716 r90 bottom
R83 "CSNL1206FT2L00" 1206 6374.27,2209.56 r0 bottom
R84 "CSNL1206FT2L00" 1206 6067.27,2564.44 r180 bottom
